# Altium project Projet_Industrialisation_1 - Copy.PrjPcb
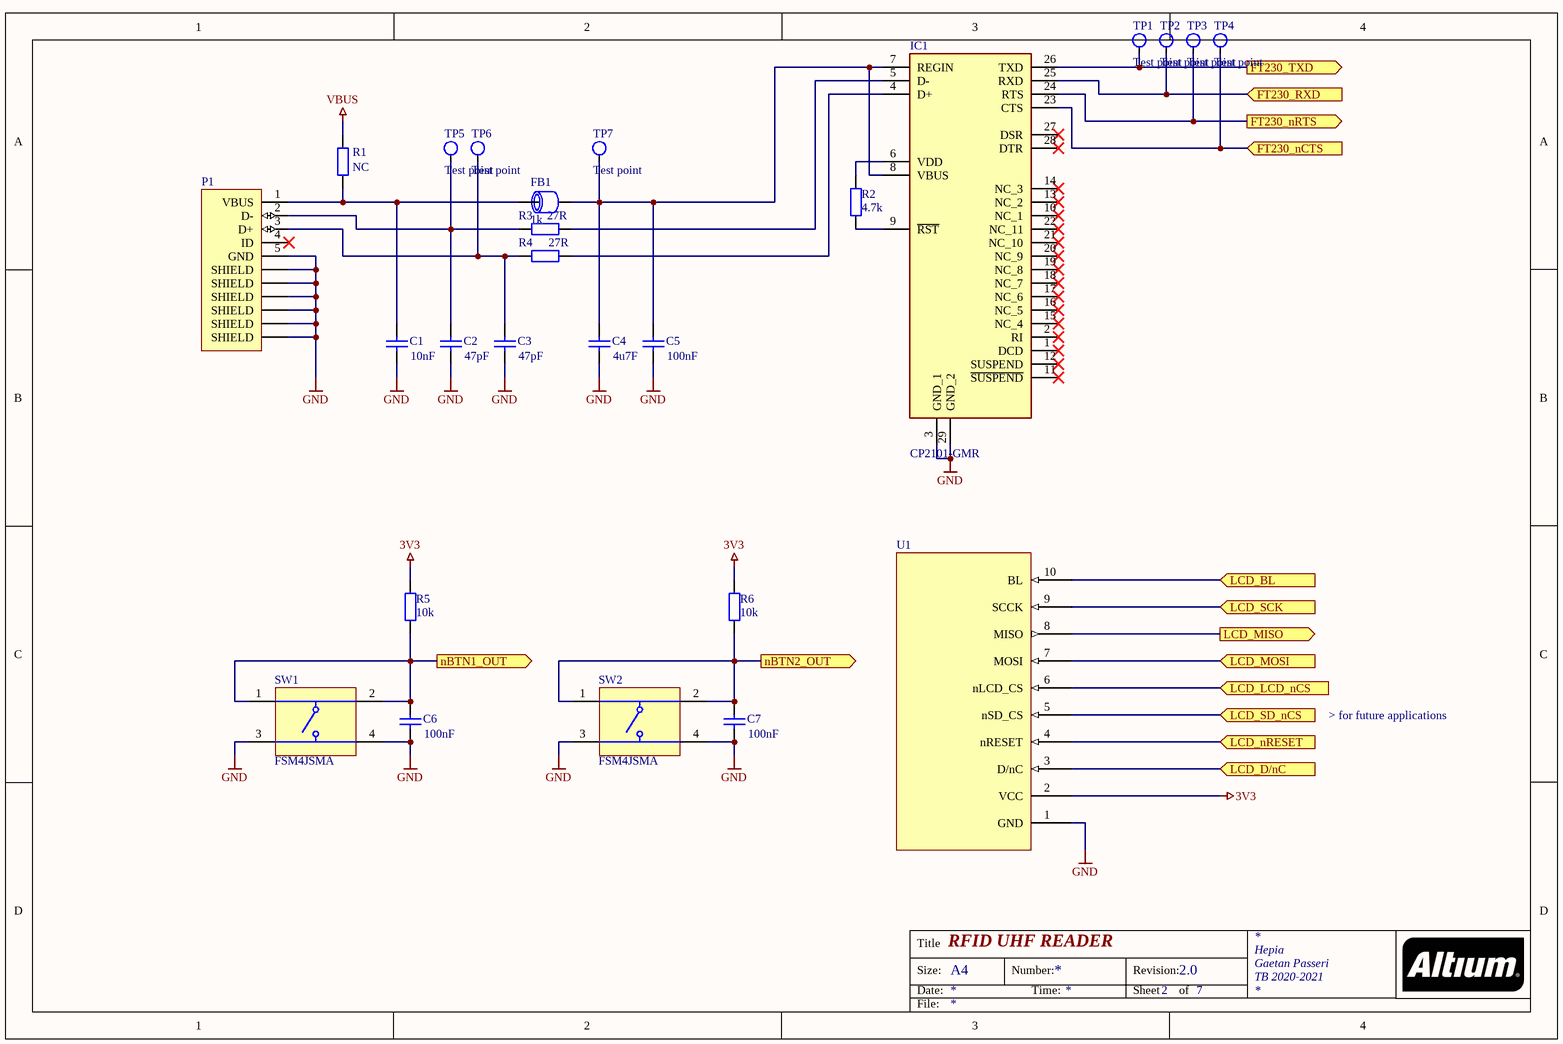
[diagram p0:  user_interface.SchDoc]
7 sheets, 252 parts. Net scope: hierarchical (ports join the sheet entries above them; power ports are global).
Board file:  baseStation.PcbDoc
Sheets:
   user_interface.SchDoc
   rf_interface.SchDoc
   microcontroller.SchDoc
   ext_power_amplifier.SchDoc
   coupling.SchDoc
   baseStation.SchDoc
   alimentation.SchDoc

## Sheet  user_interface.SchDoc: RFID UHF READER
size A4; Date: 19.03.2021; Author: Gaetan Passeri; CompanyName: HEPIA; DrawnBy: Gaetan Passeri; Address1: Hepia; Address2: Gaetan Passeri; Address3: TB 2020-2021; Revision: 2.0; SheetNumber: 2; SheetTotal: 7

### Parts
C1  value 10nF  [FP-C0603C-CF-IPC_B]  (hidden comment: Cap)
C2  value 47pF  [FP-C0603C-CF-IPC_B]  (hidden comment: Cap)
C3  value 47pF  [FP-C0603C-CF-IPC_B]  (hidden comment: Cap)
C4  value 4u7F  [FP-C0603C-CF-IPC_B]  (hidden comment: Cap)
C5  value 100nF  [FP-C0603C-CF-IPC_B]  (hidden comment: Cap)
C6  value 100nF  [FP-C0603C-CF-IPC_B]  (hidden comment: Cap)
C7  value 100nF  [FP-C0603C-CF-IPC_B]  (hidden comment: Cap)
FB1  1k  [L0402-RF]
IC1  CP2101-GMR  [QFN50P500X500X100-29N-D]
P1  47346-0001  [MOLEX_47346-0001]  (value not drawn)
R1  value NC  [FP-RC1608-IPC_B]
R2  value 4.7k  [FP-RC1608-IPC_B]
R3  value 27R  [FP-RC1608-IPC_B]
R4  value 27R  [FP-RC1608-IPC_B]
R5  value 10k  [FP-RC1608-IPC_B]
R6  value 10k  [FP-RC1608-IPC_B]
SW1  FSM4JSMA  [RKB2SJK250SMTRLFS]
SW2  FSM4JSMA  [RKB2SJK250SMTRLFS]
TP1  Test point  [PIN_DE_TEST]
TP2  Test point  [PIN_DE_TEST]
TP3  Test point  [PIN_DE_TEST]
TP4  Test point  [PIN_DE_TEST]
TP5  Test point  [PIN_DE_TEST]
TP6  Test point  [PIN_DE_TEST]
TP7  Test point  [PIN_DE_TEST]
U1  (no value)  [Adafruit_1480]

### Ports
FT230_nCTS (in), FT230_nRTS (out), FT230_RXD (in), FT230_TXD (out), LCD_BL (in), LCD_D/nC (in), LCD_LCD_nCS (in), LCD_MISO (out), LCD_MOSI (in), LCD_nRESET (in), LCD_SCK (in), LCD_SD_nCS (in), nBTN1_OUT (out), nBTN2_OUT (out)

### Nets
3V3: R5.2 R6.2 U1.2(VCC)
GND: C1.1 C2.1 C3.1 C4.1 C5.1 C6.1 C7.1 IC1.3(GND_1) IC1.29(GND_2) P1.5(GND) P1.SH1(SHIELD) P1.SH2(SHIELD) P1.SH3(SHIELD) P1.SH4(SHIELD) P1.SH5(SHIELD) P1.SH6(SHIELD) SW1.3 SW1.4 SW2.3 SW2.4 U1.1(GND)
VBUS: R1.2
NetC1_2: C1.2 FB1.1 P1.1(VBUS) R1.1
NetC2_2: C2.2 P1.2(D-) R3.1 TP5.1(tp)
NetC3_2: C3.2 P1.3(D+) R4.1 TP6.1(tp)
NetC4_2: C4.2 C5.2 FB1.2 IC1.7(REGIN) IC1.8(VBUS) TP7.1(tp)
NetC6_2: C6.2 R5.1 SW1.1 SW1.2 ; port nBTN1_OUT
NetC7_2: C7.2 R6.1 SW2.1 SW2.2 ; port nBTN2_OUT
NetIC1_4: IC1.4(D+) R4.2
NetIC1_5: IC1.5(D-) R3.2
NetIC1_6: IC1.6(VDD) R2.2
NetIC1_9: IC1.9(~{RST}) R2.1
NetIC1_23: IC1.23(CTS) TP4.1(tp) ; port FT230_nCTS
NetIC1_24: IC1.24(RTS) TP3.1(tp) ; port FT230_nRTS
NetIC1_25: IC1.25(RXD) TP2.1(tp) ; port FT230_RXD
NetIC1_26: IC1.26(TXD) TP1.1(tp) ; port FT230_TXD
NetU1_3: U1.3(D/nC) ; port LCD_D/nC
NetU1_4: U1.4(nRESET) ; port LCD_nRESET
NetU1_5: U1.5(nSD_CS) ; port LCD_SD_nCS
NetU1_6: U1.6(nLCD_CS) ; port LCD_LCD_nCS
NetU1_7: U1.7(MOSI) ; port LCD_MOSI
NetU1_8: U1.8(MISO) ; port LCD_MISO
NetU1_9: U1.9(SCCK) ; port LCD_SCK
NetU1_10: U1.10(BL) ; port LCD_BL

Not connected (* = marked no-connect by the designer): IC1 1(DCD)* 2(RI)* 10(NC_1)* 11(~{SUSPEND})* 12(SUSPEND)* 13(NC_2)* 14(NC_3)* 15(NC_4)* 16(NC_5)* 17(NC_6)* 18(NC_7)* 19(NC_8)* 20(NC_9)* 21(NC_10)* 22(NC_11)* 27(DSR)* 28(DTR)*; P1 4(ID)*

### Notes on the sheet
- > for future applications

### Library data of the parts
C1-C7 = Cap: Capacitor
FB1 = BLM15HG102SN1D: FERRITE BEAD 1 KOHM 0402 1LN; Manufacturer: Murata Electronics North America; Filter Type: Signal Line; Number of Lines: 1; Impedance @ Frequency: 1 kOhm @ 100MHz; Current Rating (Max): 250mA; DC Resistance (DCR) (Max): 1.1 Ohm
IC1 = CP2101-GMR: Integrated Circuit; Manufacturer_Name: Silicon Labs
P1 = 47346-0001: USB - micro B USB 2.0 Receptacle Connector 5 Position Surface Mount, Right Angle; MF: Molex
R1-R6 = Res2: Resistor
SW1 SW2 = CMP-2000-05602-2: Swicth, SPST, 24 V, -35 to 85 degC, 4-Pin SMD, RoHS, Tape and Reel; Manufacturer: TE Connectivity; Switch Travel: 0.25mm; Mechanical Life: 100000Cycles; Contact Current Rating: 50mA; Operating Force: 1.57N; Actuator Material: Polyamide; Contact Resistance: 100mOhm; Voltage Rating: 24V; Illumination Type: Illuminated; Actuator Length: 0.055inch; Max Voltage Rating (DC): 12V; Case\/Package: SMD/SMT
TP1-TP7 = TestPoint
U1 = Adafruit_1480: LCD Module Adafruit 1480, SPI 320x240p 2.2"

## Sheet  rf_interface.SchDoc: RFID UHF READER
size A3; Author: Gaetan Passeri; CompanyName: Hepia; Address1: Hepia; Address2: Gaetan Passeri; Address3: TB 2020-2021; Revision: 2.0; SheetNumber: 3; SheetTotal: 7
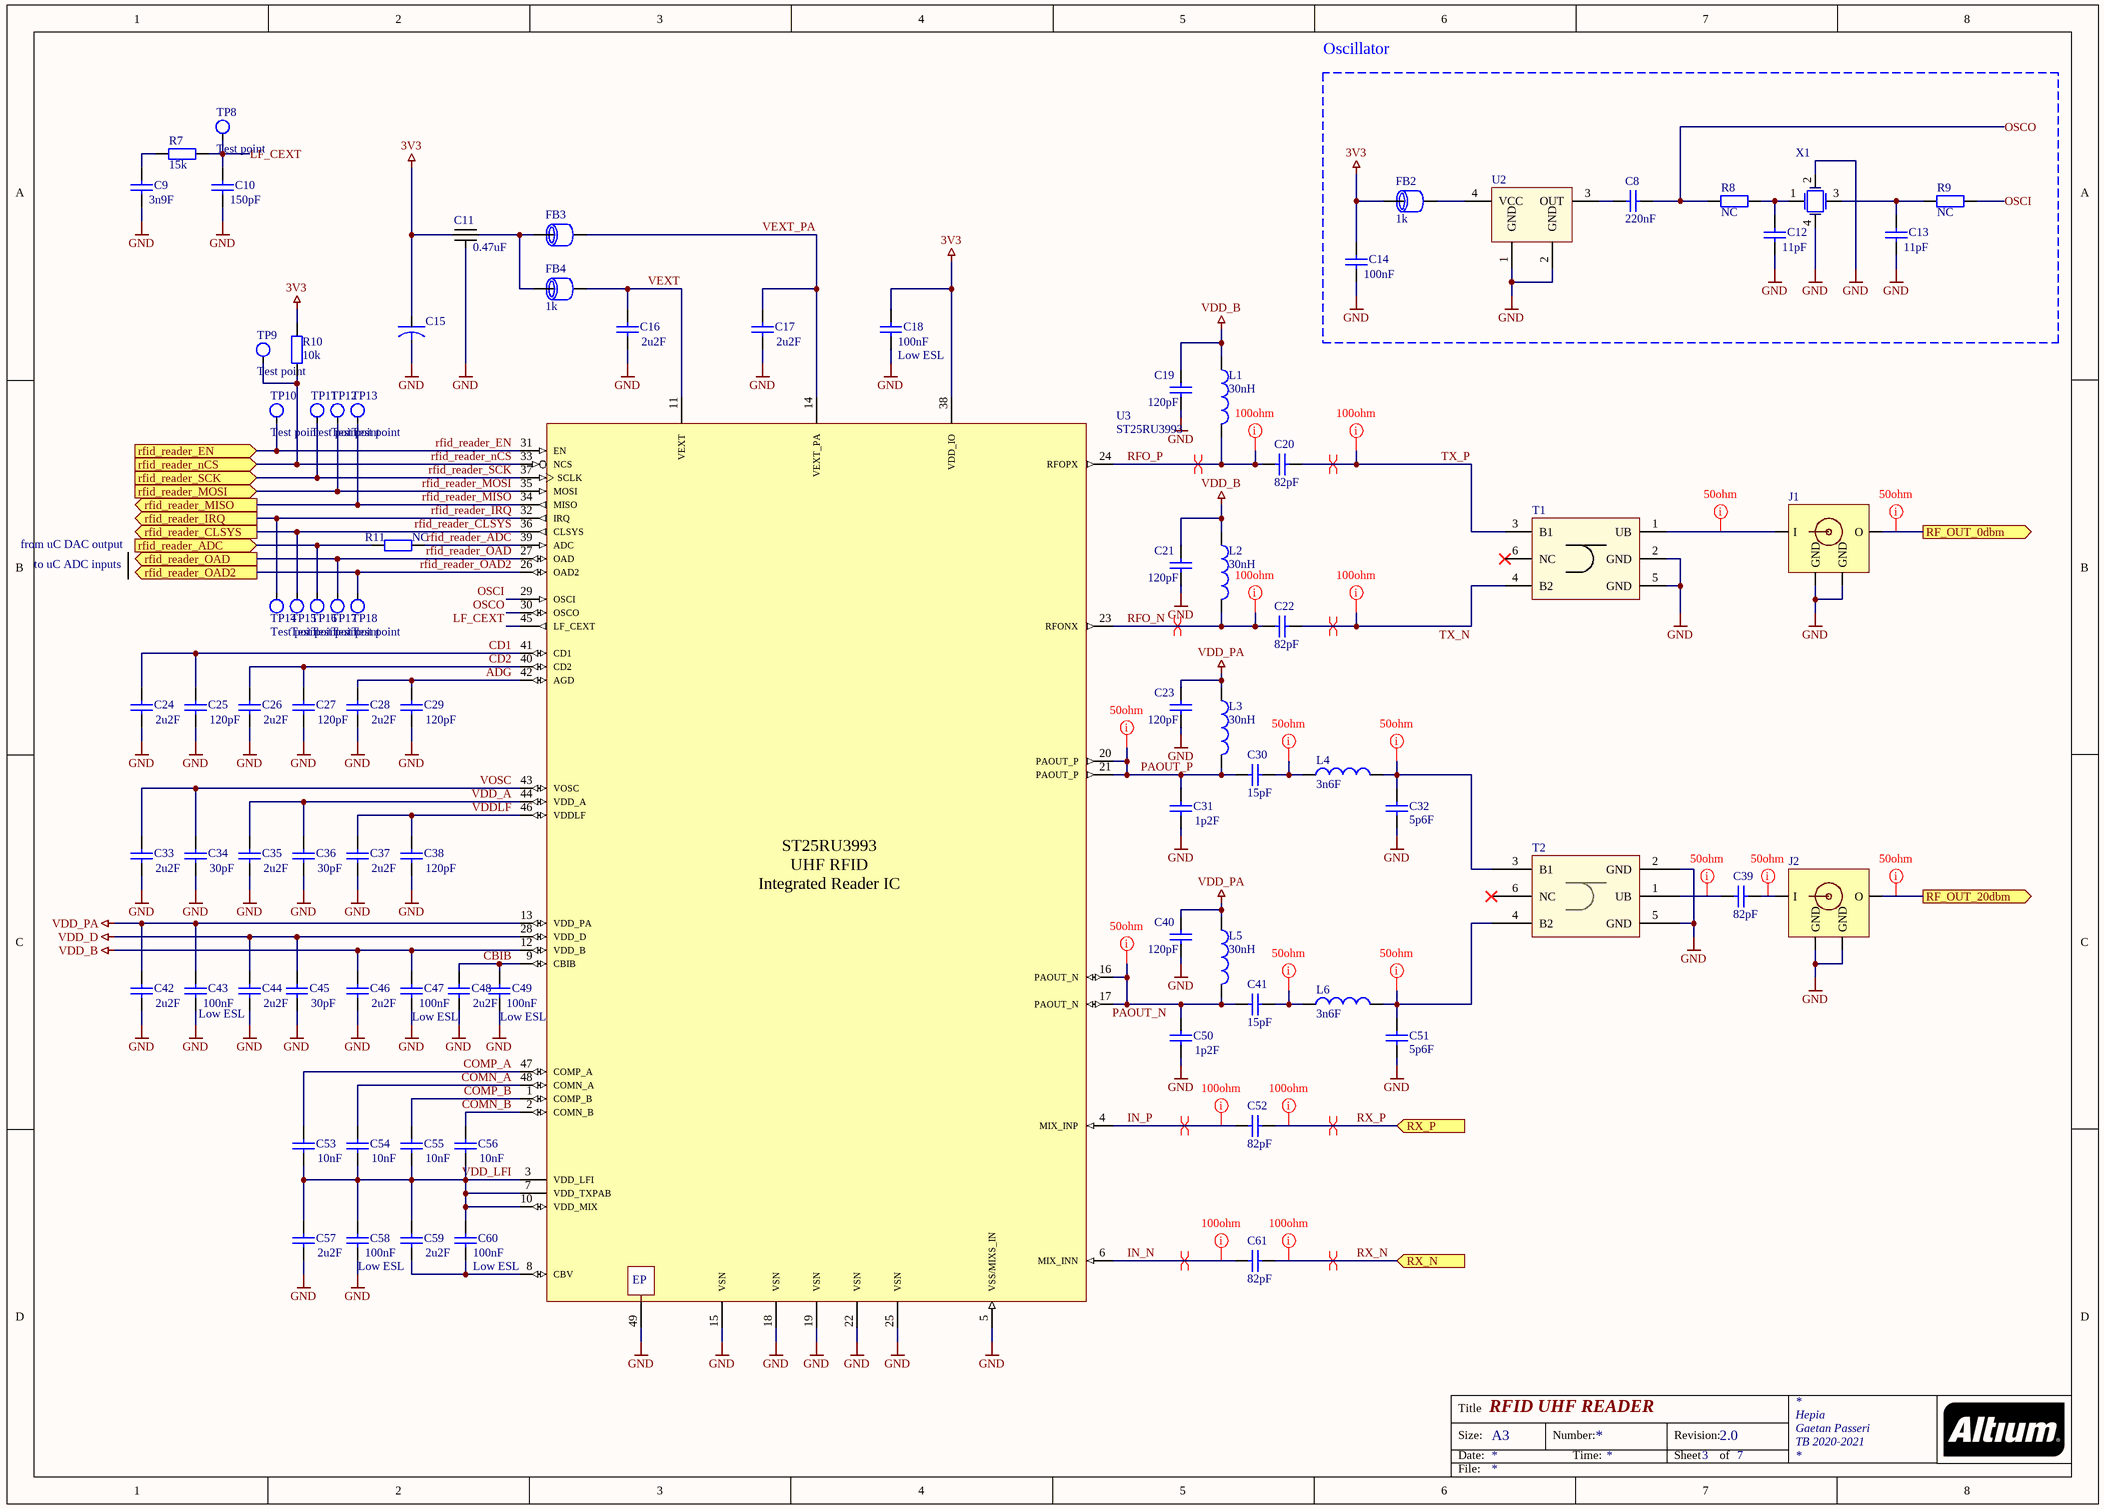
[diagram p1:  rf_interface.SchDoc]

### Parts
C8  value 220nF  [FP-C0603C-CF-IPC_B]
C9  value 3n9F  [FP-PRF15-0_05-IPC_A]
C10  value 150pF  [FP-PRF15-0_05-IPC_A]
C11  0.47uF  [NFM18PS]
C12  value 11pF  [FP-C0603C-CF-IPC_B]
C13  value 11pF  [FP-C0603C-CF-IPC_B]
C14  value 100nF  [FP-C0603C-CF-IPC_B]
C15  (no value)  [2917(7343)]
C16  value 2u2F  [FP-PRF15-0_05-IPC_A]  (hidden comment: Cap)
C17  value 2u2F  [FP-PRF15-0_05-IPC_A]  (hidden comment: Cap)
C18  Low ESL  value 100nF  [FP-PRF15-0_05-IPC_A]
C19  value 120pF  [FP-PRF15-0_05-IPC_A]  (hidden comment: Cap)
C20  value 82pF  [FP-PRF15-0_05-IPC_A]  (hidden comment: Cap)
C21  value 120pF  [FP-PRF15-0_05-IPC_A]  (hidden comment: Cap)
C22  value 82pF  [FP-PRF15-0_05-IPC_A]  (hidden comment: Cap)
C23  value 120pF  [FP-PRF15-0_05-IPC_A]  (hidden comment: Cap)
C24  value 2u2F  [FP-PRF15-0_05-IPC_A]  (hidden comment: Cap)
C25  value 120pF  [FP-PRF15-0_05-IPC_A]  (hidden comment: Cap)
C26  value 2u2F  [FP-PRF15-0_05-IPC_A]  (hidden comment: Cap)
C27  value 120pF  [FP-PRF15-0_05-IPC_A]  (hidden comment: Cap)
C28  value 2u2F  [FP-PRF15-0_05-IPC_A]  (hidden comment: Cap)
C29  value 120pF  [FP-PRF15-0_05-IPC_A]  (hidden comment: Cap)
C30  value 15pF  [FP-PRF15-0_05-IPC_A]  (hidden comment: Cap)
C31  value 1p2F  [FP-PRF15-0_05-IPC_A]  (hidden comment: Cap)
C32  value 5p6F  [FP-PRF15-0_05-IPC_A]  (hidden comment: Cap)
C33  value 2u2F  [FP-PRF15-0_05-IPC_A]  (hidden comment: Cap)
C34  value 30pF  [FP-PRF15-0_05-IPC_A]  (hidden comment: Cap)
C35  value 2u2F  [FP-PRF15-0_05-IPC_A]  (hidden comment: Cap)
C36  value 30pF  [FP-PRF15-0_05-IPC_A]  (hidden comment: Cap)
C37  value 2u2F  [FP-PRF15-0_05-IPC_A]  (hidden comment: Cap)
C38  value 120pF  [FP-PRF15-0_05-IPC_A]  (hidden comment: Cap)
C39  value 82pF  [FP-C0603C-CF-IPC_B]  (hidden comment: Cap)
C40  value 120pF  [FP-PRF15-0_05-IPC_A]  (hidden comment: Cap)
C41  value 15pF  [FP-PRF15-0_05-IPC_A]  (hidden comment: Cap)
C42  value 2u2F  [FP-PRF15-0_05-IPC_A]  (hidden comment: Cap)
C43  Low ESL  value 100nF  [FP-PRF15-0_05-IPC_A]
C44  value 2u2F  [FP-PRF15-0_05-IPC_A]  (hidden comment: Cap)
C45  value 30pF  [FP-PRF15-0_05-IPC_A]  (hidden comment: Cap)
C46  value 2u2F  [FP-PRF15-0_05-IPC_A]  (hidden comment: Cap)
C47  Low ESL  value 100nF  [FP-PRF15-0_05-IPC_A]
C48  value 2u2F  [FP-PRF15-0_05-IPC_A]  (hidden comment: Cap)
C49  Low ESL  value 100nF  [FP-PRF15-0_05-IPC_A]
C50  value 1p2F  [FP-PRF15-0_05-IPC_A]  (hidden comment: Cap)
C51  value 5p6F  [FP-PRF15-0_05-IPC_A]  (hidden comment: Cap)
C52  value 82pF  [FP-PRF15-0_05-IPC_A]  (hidden comment: Cap)
C53  value 10nF  [FP-PRF15-0_05-IPC_A]  (hidden comment: Cap)
C54  value 10nF  [FP-PRF15-0_05-IPC_A]  (hidden comment: Cap)
C55  value 10nF  [FP-PRF15-0_05-IPC_A]  (hidden comment: Cap)
C56  value 10nF  [FP-PRF15-0_05-IPC_A]  (hidden comment: Cap)
C57  value 2u2F  [FP-PRF15-0_05-IPC_A]  (hidden comment: Cap)
C58  Low ESL  value 100nF  [FP-PRF15-0_05-IPC_A]
C59  value 2u2F  [FP-PRF15-0_05-IPC_A]  (hidden comment: Cap)
C60  Low ESL  value 100nF  [FP-PRF15-0_05-IPC_A]
C61  value 82pF  [FP-PRF15-0_05-IPC_A]  (hidden comment: Cap)
FB2  1k  [L0402-RF]
FB3  (no value)  [FB0402-RF]
FB4  1k  [L0402-RF]
J1  (no value)  [MS-156HF]
J2  (no value)  [MS-156HF]
L1  value 30nH  [FP-LQG15HH_02-IPC_A]  (hidden comment: Inductor)
L2  value 30nH  [FP-LQG15HH_02-IPC_A]  (hidden comment: Inductor)
L3  value 30nH  [FP-LQG15HH_02-IPC_A]  (hidden comment: Inductor)
L4  value 3n6F  [FP-LQG15HH_02-IPC_A]  (hidden comment: Inductor)
L5  value 30nH  [FP-LQG15HH_02-IPC_A]  (hidden comment: Inductor)
L6  value 3n6F  [FP-LQG15HH_02-IPC_A]  (hidden comment: Inductor)
R7  value 15k  [FP-RC1608-IPC_B]
R8  value NC  [FP-RC1608-IPC_B]
R9  value NC  [FP-RC1608-IPC_B]
R10  value 10k  [FP-RC1608-IPC_B]
R11  value NC  [FP-RC1608-IPC_B]
T1  (no value)  [BD0810J50100AHF]
T2  (no value)  [JTI-0900BL15C050]
TP8  Test point  [PIN_DE_TEST]
TP9  Test point  [PIN_DE_TEST]
TP10  Test point  [PIN_DE_TEST]
TP11  Test point  [PIN_DE_TEST]
TP12  Test point  [PIN_DE_TEST]
TP13  Test point  [PIN_DE_TEST]
TP14  Test point  [PIN_DE_TEST]
TP15  Test point  [PIN_DE_TEST]
TP16  Test point  [PIN_DE_TEST]
TP17  Test point  [PIN_DE_TEST]
TP18  Test point  [PIN_DE_TEST]
U2  (no value)  [TY_TYPE_2.5x2.0mm]
U3  ST25RU3993  [ST25RU3993_QFN48_0.5mm_pitch]
X1  (no value)  [NX3225SA]

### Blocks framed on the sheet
Oscillator: C8 C12-C14 FB2 R8 R9 U2 X1

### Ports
RF_OUT_0dbm (out), RF_OUT_20dbm (out), rfid_reader_ADC (in), rfid_reader_CLSYS (out), rfid_reader_EN (in), rfid_reader_IRQ (out), rfid_reader_MISO (out), rfid_reader_MOSI (in), rfid_reader_nCS (in), rfid_reader_OAD2 (out), rfid_reader_OAD (out), rfid_reader_SCK (in), RX_N (in), RX_P (in)

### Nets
3V3: C11.1 C14.1 C15.1 C18.1 FB2.1 R10.1 U3.38(VDD_IO)
GND: C9.2 C10.2 C11.2 C12.2 C13.2 C14.2 C15.2 C16.2 C17.2 C18.2 C19.2 C21.2 C23.2 C24.2 C25.2 C26.2 C27.2 C28.2 C29.2 C31.2 C32.1 C33.2 C34.2 C35.2 C36.2 C37.2 C38.2 C40.2 C42.2 C43.2 C44.2 C45.2 C46.2 C47.2 C48.2 C49.2 C50.2 C51.1 C57.2 C58.2 J1.G1(GND) J1.G2(GND) J2.G1(GND) J2.G2(GND) T1.2(GND) T1.5(GND) T2.2(GND) T2.5(GND) U2.1(GND) U2.2(GND) U3.5(VSS/MIXS_IN) U3.15(VSN) U3.18(VSN) U3.19(VSN) U3.22(VSN) U3.25(VSN) U3.49(EP) X1.2(GND) X1.4(GND)
VDD_B: C19.1 C21.1 C46.1 C47.1 L1.1 L2.1 U3.12(VDD_B)
VDD_D: C44.1 C45.1 U3.28(VDD_D)
VDD_PA: C23.1 C40.1 C42.1 C43.1 L3.1 L5.1 U3.13(VDD_PA)
ADG: C28.1 C29.1 U3.42(AGD)
CBIB: C48.1 C49.1 U3.9(CBIB)
CD1: C24.1 C25.1 U3.41(CD1)
CD2: C26.1 C27.1 U3.40(CD2)
COMN_A: C54.1 U3.48(COMN_A)
COMN_B: C56.1 U3.2(COMN_B)
COMP_A: C53.1 U3.47(COMP_A)
COMP_B: C55.1 U3.1(COMP_B)
IN_N: C61.1 U3.6(MIX_INN)
IN_P: C52.1 U3.4(MIX_INP)
LF_CEXT: C10.1 R7.1 TP8.1(tp) U3.45(LF_CEXT)
OSCI: R9.1 U3.29(OSCI)
OSCO: C8.2 R8.2 U3.30(OSCO)
PAOUT_N: C41.1 C50.1 L5.2 U3.16(PAOUT_N) U3.17(PAOUT_N)
PAOUT_P: C30.1 C31.1 L3.2 U3.20(PAOUT_P) U3.21(PAOUT_P)
rfid_reader_ADC: R11.2 U3.39(ADC)
rfid_reader_CLSYS: TP15.1(tp) U3.36(CLSYS) ; port rfid_reader_CLSYS
rfid_reader_EN: TP10.1(tp) U3.31(EN) ; port rfid_reader_EN
rfid_reader_IRQ: TP14.1(tp) U3.32(IRQ) ; port rfid_reader_IRQ
rfid_reader_MISO: TP13.1(tp) U3.34(MISO) ; port rfid_reader_MISO
rfid_reader_MOSI: TP12.1(tp) U3.35(MOSI) ; port rfid_reader_MOSI
rfid_reader_nCS: R10.2 TP9.1(tp) U3.33(NCS) ; port rfid_reader_nCS
rfid_reader_OAD: TP17.1(tp) U3.27(OAD) ; port rfid_reader_OAD
rfid_reader_OAD2: TP18.1(tp) U3.26(OAD2) ; port rfid_reader_OAD2
rfid_reader_SCK: TP11.1(tp) U3.37(SCLK) ; port rfid_reader_SCK
RFO_N: C22.1 L2.2 U3.23(RFONX)
RFO_P: C20.1 L1.2 U3.24(RFOPX)
RX_N: C61.2 ; port RX_N
RX_P: C52.2 ; port RX_P
TX_N: C22.2 T1.4(B2)
TX_P: C20.2 T1.3(B1)
VDD_A: C35.1 C36.1 U3.44(VDD_A)
VDD_LFI: C53.2 C54.2 C55.2 C56.2 C57.1 C58.1 C59.1 C60.1 U3.3(VDD_LFI) U3.7(VDD_TXPAB) U3.10(VDD_MIX)
VDDLF: C37.1 C38.1 U3.46(VDDLF)
VEXT: C16.1 FB4.2 U3.11(VEXT)
VEXT_PA: C17.1 FB3.2 U3.14(VEXT_PA)
VOSC: C33.1 C34.1 U3.43(VOSC)
NetC8_1: C8.1 U2.3(OUT)
NetC9_1: C9.1 R7.2
NetC11_3: C11.3 FB3.1 FB4.1
NetC12_1: C12.1 R8.1 X1.1
NetC13_1: C13.1 R9.2 X1.3
NetC30_2: C30.2 L4.1
NetC32_2: C32.2 L4.2 T2.3(B1)
NetC39_1: C39.1 T2.1(UB)
NetC39_2: C39.2 J2.IN(I)
NetC41_2: C41.2 L6.1
NetC51_2: C51.2 L6.2 T2.4(B2)
NetC59_2: C59.2 C60.2 U3.8(CBV)
NetFB2_2: FB2.2 U2.4(VCC)
NetJ1_IN: J1.IN(I) T1.1(UB)
NetJ1_OUT: J1.OUT(O) ; port RF_OUT_0dbm
NetJ2_OUT: J2.OUT(O) ; port RF_OUT_20dbm
NetR11_1: R11.1 TP16.1(tp) ; port rfid_reader_ADC

Not connected (* = marked no-connect by the designer): T1 6(NC)*; T2 6(NC)*

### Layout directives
rule Impedance Constraint [Min = 50.00    Max = 50.00    ]: NetC30_2, NetC32_2, NetC39_1, NetC39_2, NetC41_2, NetC51_2, NetJ1_IN, NetJ1_OUT, NetJ2_OUT, PAOUT_N, PAOUT_P
rule Impedance Constraint [Min = 100.0    Max = 100.0    ]: IN_N, IN_P, RFO_N, RFO_P, RX_N, RX_P, TX_N, TX_P
differential pair: IN_N, IN_P, RFO_N, RFO_P, RX_N, RX_P, TX_N, TX_P

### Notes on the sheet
- (near C12) The TCXO is used by default. To use crystal instead, unconnect C ...(220nF) and connect two 0ohms.
- from uC DAC output
- to uC ADC inputs

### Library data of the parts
C8-C10 C12-C14 C16-C61 = Cap: type : free, 0603, 20%
C11 = NFM18PS474R0J3D_1: CAP FEEDTHRU 0.47UF 6.3V 0603; Manufacturer: Murata Electronics North America; Capacitance: 0.47µF; Tolerance: ±20%; Current: 2A; DC Resistance (DCR) (Max): 30 mOhm; Type: Polymer; ESR (Equivalent Series Resistance): 70 mOhm; Lifetime @ Temp.: 1000 Hrs @ 105°C; Ripple Current - High Frequency: 1A @ 100kHz; Surface Mount Land Size: 0.287" L x 0.169" W (7.30mm x 4.30mm)
C15 = ECASD41C106M060K00: CAP POLYMER 10UF 20% 16V SMD; Manufacturer: Murata; Product Training Modules: Polymer Aluminum Electrolytic Capacitors Using Murata's Polymer Aluminum Capacitors to Replace Tantalum; Catalog Drawings: ECAS Series End_D4 ECAS Series Side; Featured Product: ECAS Series Polymer Aluminum Electrolytic Capacitors; EDA / CAD Models: Download from Accelerated Designs; Capacitance: 10µF; ESR (Equivalent Series Resistance): 60 mOhm @ 100kHz; Lifetime @ Temp.: 1000 Hrs @ 105°C; Polarization: Polar; Ripple Current: 1A; Surface Mount Land Size: 0.287" L x 0.169" W (7.30mm x 4.30mm); Online Catalog: ECAS Series; Other Names: 490-5482-2
FB2 FB4 = BLM15HG102SN1D: as FB1 on sheet  user_interface
FB3 = BLM15PX331SN1D: FERRITE BEAD 330 OHM 0402 1LN; Manufacturer: Murata Electronics North America; Filter Type: Power Line; Current Rating (Max): 1.2A; DC Resistance (DCR) (Max): 150 mOhm
J1 J2 = MS-156HF: CONN COAX JACK STR 50 OHM SMD; Manufacturer 1: Hirose Electric Co Ltd; Manufacturer Part Number 1: MS-156HF(01); Connector Style: Coaxial Switch - 4mm Plug Dia; Connector Type: Receptacle, Female Socket; Contact Termination: Solder; Impedance: 50 Ohm; Frequency - Max: 6GHz; Body Material: Phosphor Bronze; Body Finish: Gold; Center Contact Material: Beryllium Copper; Dielectric Material: Polyamide (PA), Nylon 6T; Coupler Type: Standard; Frequency: 700MHz ~ 1GHz; Coupling Factor: 10.9dB; Insertion Loss: 0.21dB; Power - Max: 2W; Return Loss: 17.5dB; Exact Component Match: yes
L1-L6 = Inductor: Code_IEC: 1005
R7-R11 = Res2: Resistor
T1 = BD0810J50100AHF: XFRMR BALUN RF 800-1000MHZ 0805; Manufacturer: Anaren; Frequency Range: 800MHz ~ 1GHz; Impedance - Unbalanced/Balanced: 50 / 100 Ohm; Phase Difference: 1°; Insertion Loss (Max): 0.95dB; Return Loss (Min): 13dB
T2 = 1:1 BALUN 900MHZ - 0900BL15C050: 1:1 BALUN- 900MHZ 50/50 Ohm; Manufacturer: Johanson Technology Inc; Manufacturer Part Number: 0900BL15C050E; Component_Description: BALUN GSM/DCS/PCS/CDMA 900MHZ; Frequency Range: 800 ~ 1000MHz; Phase Difference: 180° ±10; Insertion Loss (Max): 1.2dB; Return Loss (Min): 9.5dB
TP8-TP18 = TestPoint
U2 = 7Q-20.000MCN-T: OSC TCXO 20.000MHZ CLPD SNWV SMD; Manufacturer: Taitien; Manufacturer Part Number: TXEAADSANF-20.000000; Output: Clipped Sine Wave; Voltage - Supply: 2.8 V ~ 3.3 V; Frequency Stability: ±500ppb; Current - Supply (Max): 2mA
U3 = ST25RU3993: UHF EPC CLASS1 GEN2 READER; Manufacturer: ST Microelectronics; Manufacturer Part Number: AS3993-BQFT; Frequency: 860MHz ~ 960MHz; Standards: EPC, ISO 18000-6; Voltage - Supply: 2.7 V ~ 3.6 V; Exact Component Match: yes
X1 = NX3225SA-20.000000MHZ-B2: CRYSTAL 20.0000MHZ 7.2PF SMD; Manufacturer: NDK; Frequency: 20MHz; Frequency Stability: ±15ppm; Frequency Tolerance: ±10ppm; ESR (Equivalent Series Resistance): 80 Ohm; Operating Mode: Fundamental

## Sheet  microcontroller.SchDoc: RFID UHF READER
size A3; Date: 19.03.2021; Author: Gaetan Passeri; CompanyName: HEPIA; DrawnBy: Gaetan Passeri; Address1: Hepia; Address2: Gaetan Passeri; Address3: TB 2020-2021; Revision: 2.0; SheetNumber: 4; SheetTotal: 7
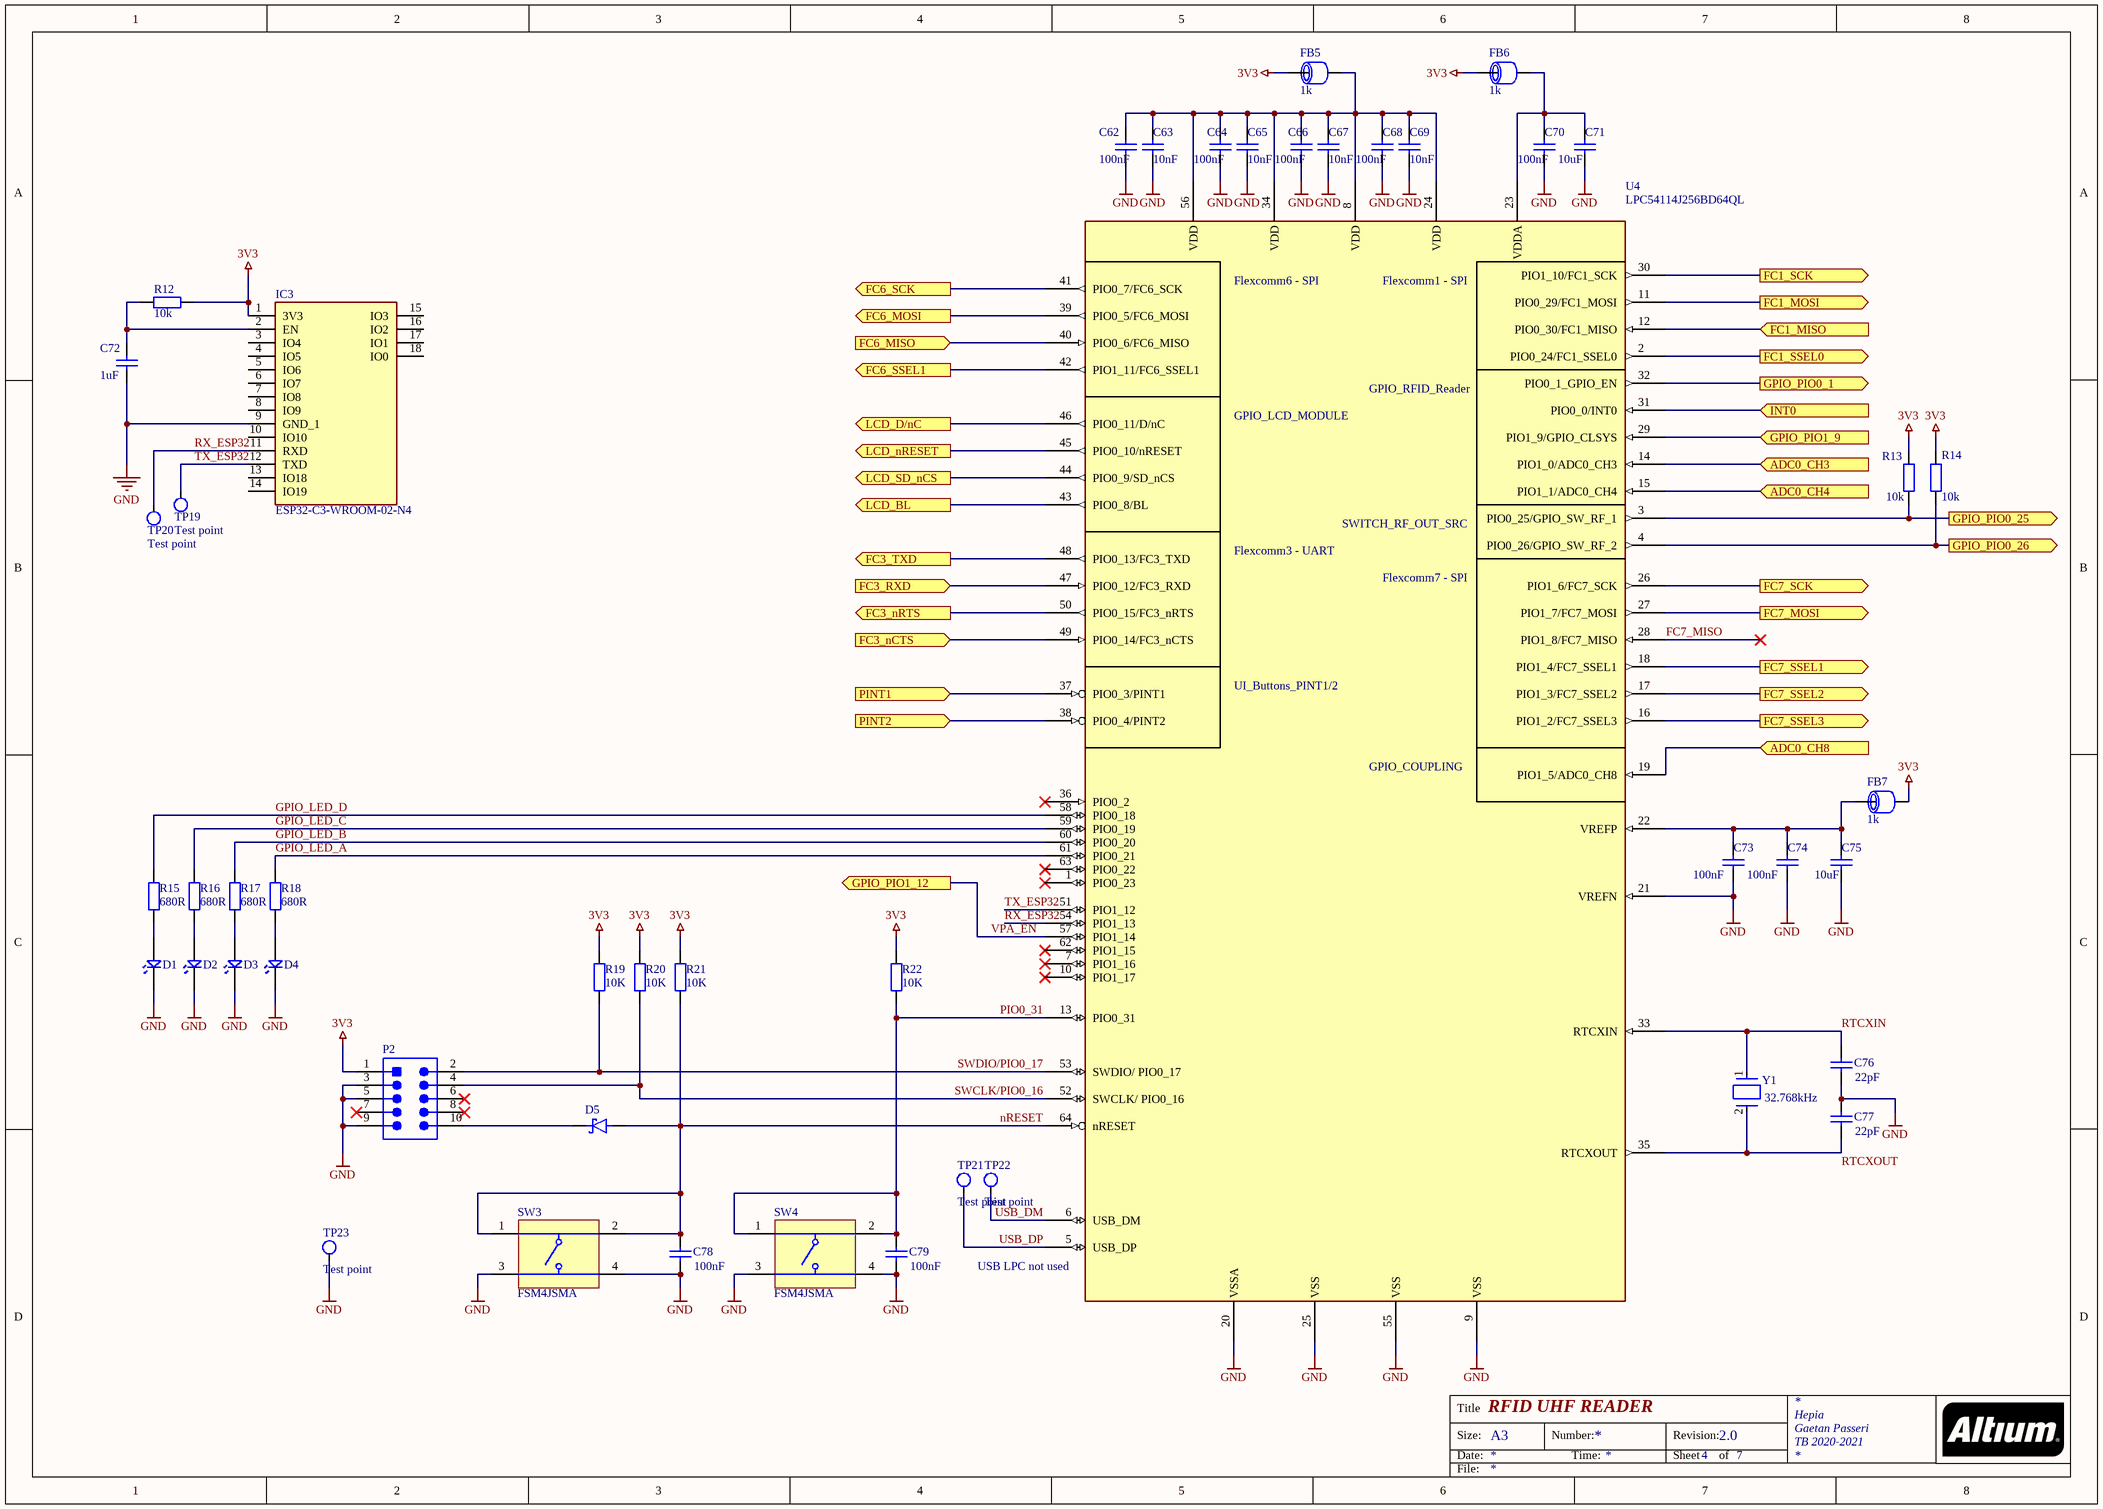
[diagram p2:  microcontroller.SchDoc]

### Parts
C62  value 100nF  [FP-C0603C-CF-IPC_A]  (hidden comment: Cap)
C63  value 10nF  [FP-C0603C-CF-IPC_A]  (hidden comment: Cap)
C64  value 100nF  [FP-C0603C-CF-IPC_A]  (hidden comment: Cap)
C65  value 10nF  [FP-C0603C-CF-IPC_A]  (hidden comment: Cap)
C66  value 100nF  [FP-C0603C-CF-IPC_A]  (hidden comment: Cap)
C67  value 10nF  [FP-C0603C-CF-IPC_A]  (hidden comment: Cap)
C68  value 100nF  [FP-C0603C-CF-IPC_A]  (hidden comment: Cap)
C69  value 10nF  [FP-C0603C-CF-IPC_A]  (hidden comment: Cap)
C70  value 100nF  [FP-C0603C-CF-IPC_A]  (hidden comment: Cap)
C71  value 10uF  [FP-C0603C-CF-IPC_A]  (hidden comment: Cap)
C72  value 1uF  [FP-C0603C-CF-IPC_A]  (hidden comment: Cap)
C73  value 100nF  [FP-C0603C-CF-IPC_A]  (hidden comment: Cap)
C74  value 100nF  [FP-C0603C-CF-IPC_A]  (hidden comment: Cap)
C75  value 10uF  [FP-C0603C-CF-IPC_A]  (hidden comment: Cap)
C76  value 22pF  [FP-C0603C-CF-IPC_A]  (hidden comment: Cap)
C77  value 22pF  [FP-C0603C-CF-IPC_A]  (hidden comment: Cap)
C78  value 100nF  [FP-C0603C-CF-IPC_B]  (hidden comment: Cap)
C79  value 100nF  [FP-C0603C-CF-IPC_B]  (hidden comment: Cap)
D1  (no value)  [LTST-C170KRKT_V]
D2  (no value)  [LTST-C170KRKT_V]
D3  (no value)  [LTST-C170KRKT_V]
D4  (no value)  [LTST-C170KRKT_V]
D5  (no value)  [SOD3715X135N]
FB5  1k  [L0402-RF]
FB6  1k  [L0402-RF]
FB7  1k  [L0402-RF]
IC3  ESP32-C3-WROOM-02-N4  [ESP32C3WROOM02N4]
P2  (no value)  [HDR2X5_SMT]
R12  value 10k  [FP-RC1608-IPC_B]
R13  value 10k  [FP-RC1608-IPC_B]
R14  value 10k  [FP-RC1608-IPC_B]
R15  value 680R  [FP-RC1608-IPC_B]
R16  value 680R  [FP-RC1608-IPC_B]
R17  value 680R  [FP-RC1608-IPC_B]
R18  value 680R  [FP-RC1608-IPC_B]
R19  value 10K  [FP-RC1608-IPC_A]
R20  value 10K  [FP-RC1608-IPC_A]
R21  value 10K  [FP-RC1608-IPC_A]
R22  value 10K  [FP-RC1608-IPC_A]
SW3  FSM4JSMA  [RKB2SJK250SMTRLFS]
SW4  FSM4JSMA  [RKB2SJK250SMTRLFS]
TP19  Test point  [PIN_DE_TEST]
TP20  Test point  [PIN_DE_TEST]
TP21  Test point  [PIN_DE_TEST]
TP22  Test point  [PIN_DE_TEST]
TP23  Test point  [PIN_DE_TEST]
U4  LPC54114J256BD64QL  [QFP50P1200X1200X160-64N]
Y1  Frequency: 32.768kHz  [FP-ECX-34Q-MFG]

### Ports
ADC0_CH3 (in), ADC0_CH4 (in), ADC0_CH8 (in), FC1_MISO (in), FC1_MOSI (out), FC1_SCK (out), FC1_SSEL0 (out), FC3_nCTS (in), FC3_nRTS (out), FC3_RXD (in), FC3_TXD (out), FC6_MISO (in), FC6_MOSI (out), FC6_SCK (out), FC6_SSEL1 (out), FC7_MOSI (out), FC7_SCK (out), FC7_SSEL1 (out), FC7_SSEL2 (out), FC7_SSEL3 (out), GPIO_PIO0_1 (out), GPIO_PIO0_25 (out), GPIO_PIO0_26 (out), GPIO_PIO1_9 (in), GPIO_PIO1_12 (out), INT0 (in), LCD_BL (out), LCD_D/nC (out), LCD_nRESET (out), LCD_SD_nCS (out), PINT1 (in), PINT2 (in)

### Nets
3V3: FB5.1 FB6.1 FB7.2 IC3.1(3V3) P2.1 R12.2 R13.1 R14.1 R19.2 R20.2 R21.2 R22.2
GND: C62.1 C63.1 C64.1 C65.1 C66.1 C67.1 C68.1 C69.1 C70.1 C71.1 C72.1 C73.1 C74.1 C75.1 C76.1 C77.2 C78.1 C79.1 D1.K D2.K D3.K D4.K IC3.9(GND_1) P2.3 P2.5 P2.9 SW3.3 SW3.4 SW4.3 SW4.4 TP23.1(tp) U4.9(VSS) U4.20(VSSA) U4.21(VREFN) U4.25(VSS) U4.55(VSS)
FC7_MISO: U4.28(PIO1_8/FC7_MISO)
GPIO_LED_A: R18.2 U4.61(PIO0_21)
GPIO_LED_B: R17.2 U4.60(PIO0_20)
GPIO_LED_C: R16.2 U4.59(PIO0_19)
GPIO_LED_D: R15.2 U4.58(PIO0_18)
nRESET: C78.2 D5.A R21.1 SW3.1 SW3.2 U4.64(nRESET)
PIO0_31: C79.2 R22.1 SW4.1 SW4.2 U4.13(PIO0_31)
RTCXIN: C76.2 U4.33(RTCXIN) Y1.1(In/Out)
RTCXOUT: C77.1 U4.35(RTCXOUT) Y1.2(Out/In)
RX_ESP32: IC3.11(RXD) TP20.1(tp) U4.54(PIO1_13)
SWCLK/PIO0_16: P2.4 R20.1 U4.52(SWCLK/_PIO0_16)
SWDIO/PIO0_17: P2.2 R19.1 U4.53(SWDIO/_PIO0_17)
TX_ESP32: IC3.12(TXD) TP19.1(tp) U4.51(PIO1_12)
USB_DM: TP22.1(tp) U4.6(USB_DM)
USB_DP: TP21.1(tp) U4.5(USB_DP)
VPA_EN: U4.57(PIO1_14) ; port GPIO_PIO1_12
NetC62_2: C62.2 C63.2 C64.2 C65.2 C66.2 C67.2 C68.2 C69.2 FB5.2 U4.8(VDD) U4.24(VDD) U4.34(VDD) U4.56(VDD)
NetC70_2: C70.2 C71.2 FB6.2 U4.23(VDDA)
NetC72_2: C72.2 IC3.2(EN) R12.1
NetC73_2: C73.2 C74.2 C75.2 FB7.1 U4.22(VREFP)
NetD1_A: D1.A R15.1
NetD2_A: D2.A R16.1
NetD3_A: D3.A R17.1
NetD4_A: D4.A R18.1
NetD5_K: D5.K P2.10
NetR13_2: R13.2 U4.3(PIO0_25/GPIO_SW_RF_1) ; port GPIO_PIO0_25
NetR14_2: R14.2 U4.4(PIO0_26/GPIO_SW_RF_2) ; port GPIO_PIO0_26
NetU4_2: U4.2(PIO0_24/FC1_SSEL0) ; port FC1_SSEL0
NetU4_11: U4.11(PIO0_29/FC1_MOSI) ; port FC1_MOSI
NetU4_12: U4.12(PIO0_30/FC1_MISO) ; port FC1_MISO
NetU4_14: U4.14(PIO1_0/ADC0_CH3) ; port ADC0_CH3
NetU4_15: U4.15(PIO1_1/ADC0_CH4) ; port ADC0_CH4
NetU4_16: U4.16(PIO1_2/FC7_SSEL3) ; port FC7_SSEL3
NetU4_17: U4.17(PIO1_3/FC7_SSEL2) ; port FC7_SSEL2
NetU4_18: U4.18(PIO1_4/FC7_SSEL1) ; port FC7_SSEL1
NetU4_19: U4.19(PIO1_5/ADC0_CH8) ; port ADC0_CH8
NetU4_26: U4.26(PIO1_6/FC7_SCK) ; port FC7_SCK
NetU4_27: U4.27(PIO1_7/FC7_MOSI) ; port FC7_MOSI
NetU4_29: U4.29(PIO1_9/GPIO_CLSYS) ; port GPIO_PIO1_9
NetU4_30: U4.30(PIO1_10/FC1_SCK) ; port FC1_SCK
NetU4_31: U4.31(PIO0_0/INT0) ; port INT0
NetU4_32: U4.32(PIO0_1_GPIO_EN) ; port GPIO_PIO0_1
NetU4_37: U4.37(PIO0_3/PINT1) ; port PINT1
NetU4_38: U4.38(PIO0_4/PINT2) ; port PINT2
NetU4_39: U4.39(PIO0_5/FC6_MOSI) ; port FC6_MOSI
NetU4_40: U4.40(PIO0_6/FC6_MISO) ; port FC6_MISO
NetU4_41: U4.41(PIO0_7/FC6_SCK) ; port FC6_SCK
NetU4_42: U4.42(PIO1_11/FC6_SSEL1) ; port FC6_SSEL1
NetU4_43: U4.43(PIO0_8/BL) ; port LCD_BL
NetU4_44: U4.44(PIO0_9/SD_nCS) ; port LCD_SD_nCS
NetU4_45: U4.45(PIO0_10/nRESET) ; port LCD_nRESET
NetU4_46: U4.46(PIO0_11/D/nC) ; port LCD_D/nC
NetU4_47: U4.47(PIO0_12/FC3_RXD) ; port FC3_RXD
NetU4_48: U4.48(PIO0_13/FC3_TXD) ; port FC3_TXD
NetU4_49: U4.49(PIO0_14/FC3_nCTS) ; port FC3_nCTS
NetU4_50: U4.50(PIO0_15/FC3_nRTS) ; port FC3_nRTS

Not connected (* = marked no-connect by the designer): IC3 3(IO4) 4(IO5) 5(IO6) 6(IO7) 7(IO8) 8(IO9) 10(IO10) 13(IO18) 14(IO19) 15(IO3) 16(IO2) 17(IO1) 18(IO0); P2 6* 7* 8*; U4 1(PIO0_23)* 7(PIO1_16)* 10(PIO1_17)* 36(PIO0_2)* 62(PIO1_15)* 63(PIO0_22)*

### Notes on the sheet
- boot configuration : from valid code in flash. see chapter 3.2 of datasheet.
- CX1 = CX2 = 2CL -  (CPad + CParasitic)
  Where:
  CL - Crystal load capacitance
  CPad - Pad capacitance of the RTCXIN and RTCXOUT pins (3 pF).
  CParasitic – Parasitic or stray capacitance of external circuit. (Datasheet p.90)
- (near SW4) press and hold during a manuel reset to restart in ISP mode.
- (near U4) USB LPC not used

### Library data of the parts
C62-C75 C78 C79 = Cap: Capacitor
D1-D4 = LED
D5 = BAT54W-HG3-08: Schottky Diodes & Rectifiers 30V Zener SKY DIODE SOD-123; MF: Vishay Semiconductors
FB5-FB7 = BLM15HG102SN1D: as FB1 on sheet  user_interface
IC3 = ESP32-C3-WROOM-02-N4: Integrated Circuit; Manufacturer_Name: Espressif Systems
P2 = CMP-2000-05523-1: Male Header, Pitch 1.27 mm, 2 x 5 Position, Height 4.55 mm, -40 to 85 degC, RoHS, Tape and Reel; Brand: FCI; Mating Post Length: 3.05mm; Voltage Rating: 125V; Contact resistance Max: 30MOhm; Number of Positions: 10; Pitch: 1.27mm; Current Rating: 1A; Stack Height: 3mm; Mounting Angle: Vertical; Package Version: Rev. J, 03/2013
R12-R22 = Res2: Resistor
SW3 SW4 = CMP-2000-05602-2: as SW1 on sheet  user_interface
TP19-TP23 = TestPoint
Y1 = CMP-40224-000019-1: CRYSTAL 32.768KHZ 12.5PF SMD; ESR (Equivalent Series Resistance): 80kR; Frequency Tolerance: 10ppm

## Sheet  ext_power_amplifier.SchDoc: RFID UHF READER
size A4; Address1: Hepia; Address2: Gaetan Passeri; Address3: TB 2020-2021; Revision: 2.0; SheetNumber: 5; SheetTotal: 7
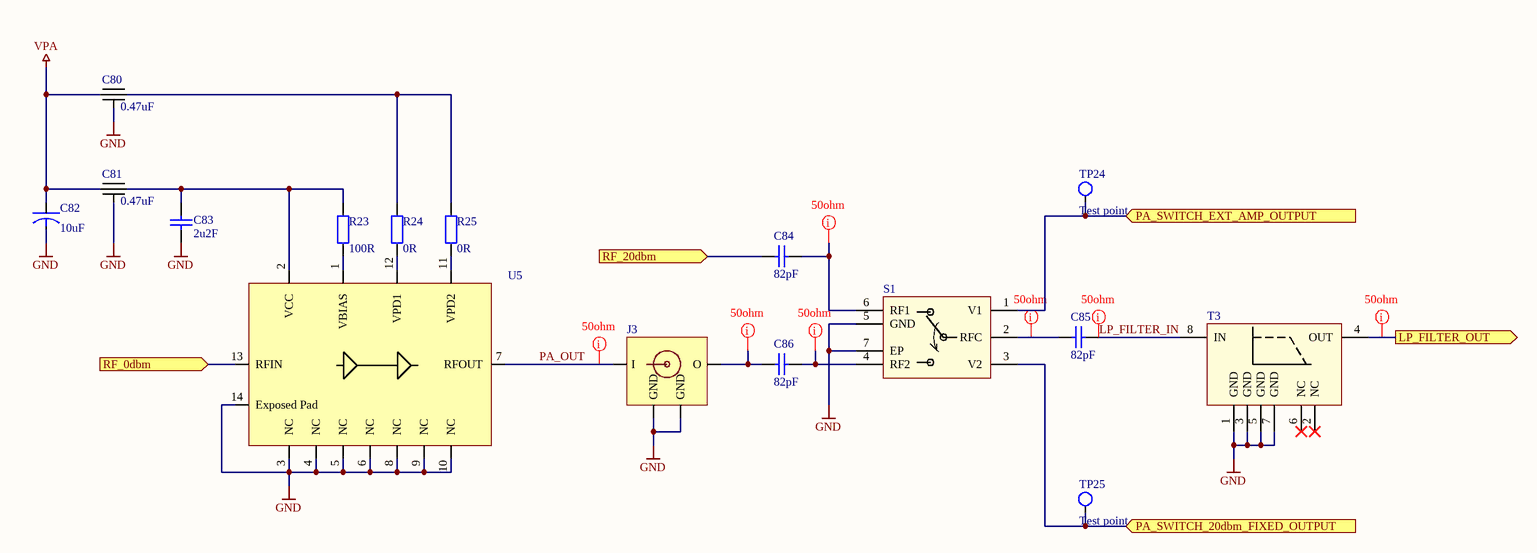
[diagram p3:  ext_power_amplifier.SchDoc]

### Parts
C80  0.47uF  [NFM18PS]
C81  0.47uF  [NFM18PS]
C82  10uF  [2917(7343)]
C83  value 2u2F  [FP-C0603C-CF-IPC_B]  (hidden comment: Cap)
C84  value 82pF  [FP-C0603C-CF-IPC_B]  (hidden comment: Cap)
C85  value 82pF  [FP-C0603C-CF-IPC_B]  (hidden comment: Cap)
C86  value 82pF  [FP-C0603C-CF-IPC_B]  (hidden comment: Cap)
J3  (no value)  [MS-156HF]
R23  value 100R  [FP-RC1608-IPC_B]  (hidden comment: Res2)
R24  value 0R  [FP-RC1608-IPC_B]  (hidden comment: Res2)
R25  value 0R  [FP-RC1608-IPC_B]  (hidden comment: Res2)
S1  (no value)  [SKY13431-374LF]
T3  (no value)  [JTI-0900LP15B0063]
TP24  Test point  [PIN_DE_TEST]
TP25  Test point  [PIN_DE_TEST]
U5  (no value)  [TQP9107]

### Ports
LP_FILTER_OUT (out), PA_SWITCH_20dbm_FIXED_OUTPUT (in), PA_SWITCH_EXT_AMP_OUTPUT (in), RF_0dbm (in), RF_20dbm (in)

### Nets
GND: C80.2 C81.2 C82.2 C83.1 J3.G1(GND) J3.G2(GND) S1.5(GND) S1.7(EP) T3.1(GND) T3.3(GND) T3.5(GND) T3.7(GND) U5.3(NC) U5.4(NC) U5.5(NC) U5.6(NC) U5.8(NC) U5.9(NC) U5.10(NC) U5.14(Exposed_Pad)
VPA: C80.1 C81.1 C82.1
LP_FILTER_IN: C85.2 T3.8(IN)
PA_OUT: J3.IN(I) U5.7(RFOUT)
NetC80_3: C80.3 R24.2 R25.2
NetC81_3: C81.3 C83.2 R23.2 U5.2(VCC)
NetC84_1: C84.1 ; port RF_20dbm
NetC84_2: C84.2 S1.6(RF1)
NetC85_1: C85.1 S1.2(RFC)
NetC86_1: C86.1 J3.OUT(O)
NetC86_2: C86.2 S1.4(RF2)
NetR23_1: R23.1 U5.1(VBIAS)
NetR24_1: R24.1 U5.12(VPD1)
NetR25_1: R25.1 U5.11(VPD2)
NetS1_1: S1.1(V1) TP24.1(tp) ; port PA_SWITCH_EXT_AMP_OUTPUT
NetS1_3: S1.3(V2) TP25.1(tp) ; port PA_SWITCH_20dbm_FIXED_OUTPUT
NetT3_4: T3.4(OUT) ; port LP_FILTER_OUT
NetU5_13: U5.13(RFIN) ; port RF_0dbm

Not connected (* = marked no-connect by the designer): T3 2(NC)* 6(NC)*

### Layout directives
rule Impedance Constraint [Min = 50.00    Max = 50.00    ]: LP_FILTER_IN, NetC84_2, NetC85_1, NetC86_1, NetC86_2, NetT3_4, PA_OUT

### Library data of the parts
C80 C81 = NFM18PS474R0J3D_1: as C11 on sheet  rf_interface
C82 = ECASD41C106M060K00: as C15 on sheet  rf_interface
C83-C86 = Cap: type : free, 0603, 20%
J3 = MS-156HF: as J1 on sheet  rf_interface
R23-R25 = Res2: Resistor
S1 = SKY13431-374LF: IC SWITCH SP2T; Manufacturer: Skyworks Solutions Inc.; Frequency - Lower: 500MHz; Isolation @ Frequency: 20dB @ 5.8GHz (typ); Insertion Loss @ Frequency: 0.8dB @ 5.8GHz; IIP3: 57dBm (typ); Circuit: SPDT; P1dB: 36dBm; Impedance: 50 Ohm; Voltage - Supply: 2.5 V ~ 5 V; RF Type: WiMax, WLAN
T3 = 0900LP15B0063: FILTER LOWPASS 863-960MHZ; Manufacturer: Johanson Technology Inc.; Manufacturer Part Number: 0900LP15B0063E
TP24 TP25 = TestPoint
U5 = TQP9107: 699 – 960 MHz 2-stage Power Amplifier; Manufacturer: Qorvo

## Sheet  coupling.SchDoc: RFID UHF READER
size A4; Address1: Hepia; Address2: Gaetan Passeri; Address3: TB 2020-2021; Revision: 2.0; SheetNumber: 6; SheetTotal: 7
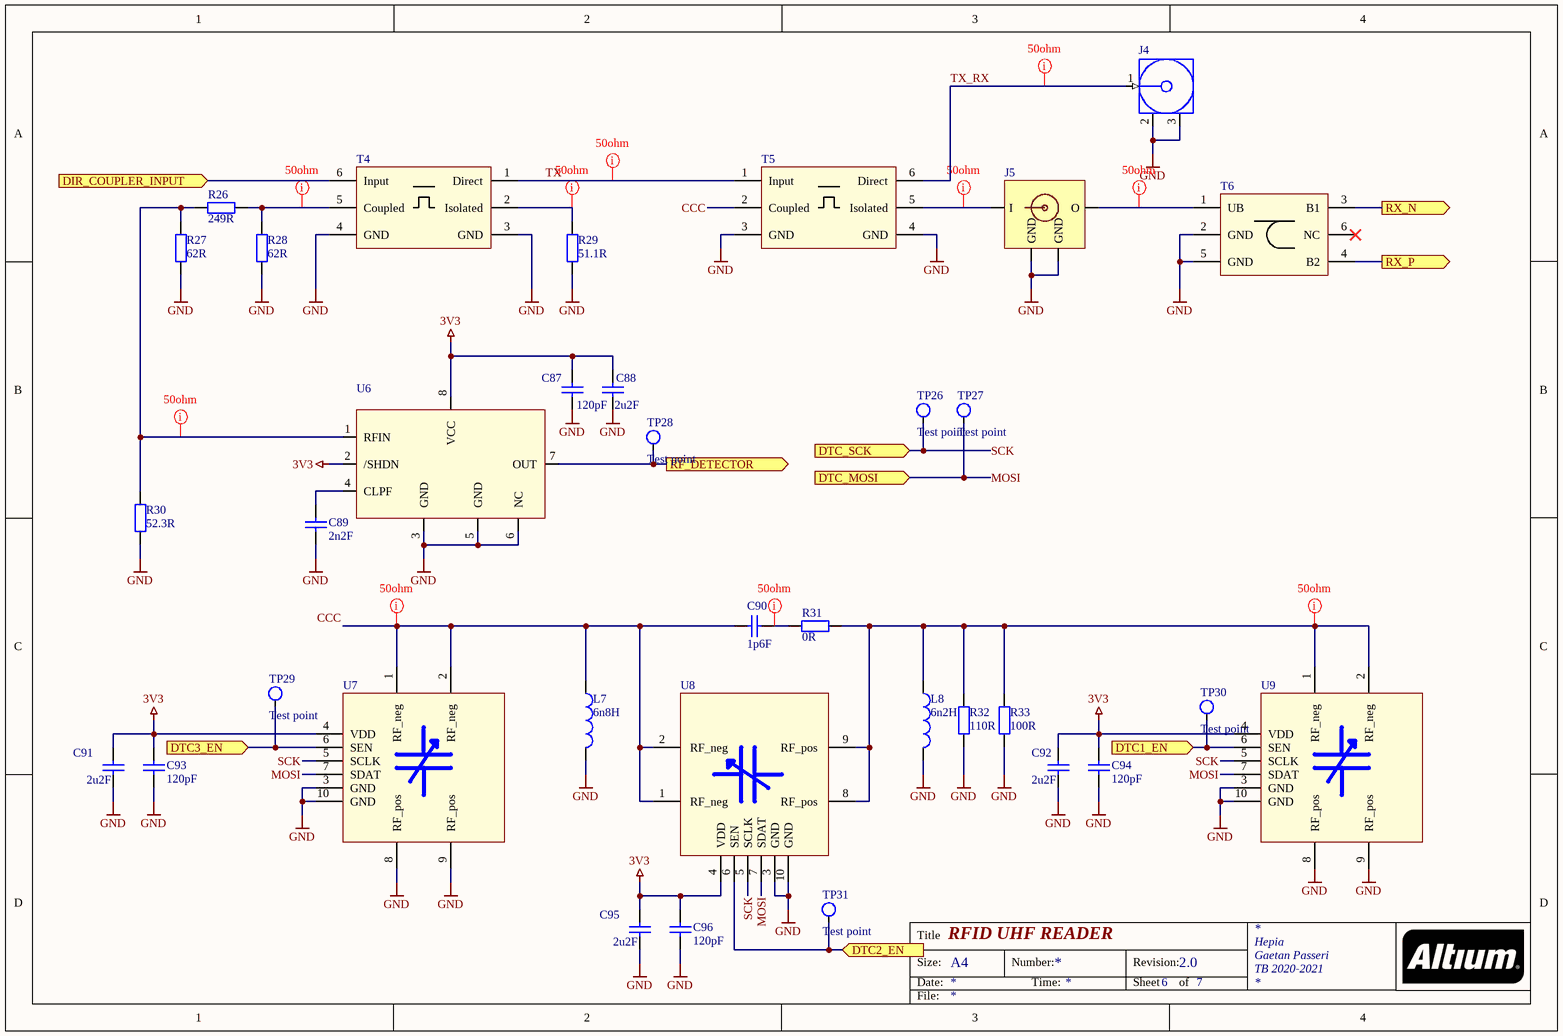
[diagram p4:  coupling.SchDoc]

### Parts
C87  value 120pF  [FP-PRF15-0_05-IPC_A]  (hidden comment: Cap)
C88  value 2u2F  [FP-PRF15-0_05-IPC_A]  (hidden comment: Cap)
C89  value 2n2F  [FP-PRF15-0_05-IPC_A]  (hidden comment: Cap)
C90  value 1p6F  [FP-PRF15-0_05-MFG]  (hidden comment: Cap)
C91  value 2u2F  [FP-PRF15-0_05-IPC_A]  (hidden comment: Cap)
C92  value 2u2F  [FP-PRF15-0_05-IPC_A]  (hidden comment: Cap)
C93  value 120pF  [FP-PRF15-0_05-IPC_A]  (hidden comment: Cap)
C94  value 120pF  [FP-PRF15-0_05-IPC_A]  (hidden comment: Cap)
C95  value 2u2F  [FP-PRF15-0_05-IPC_A]  (hidden comment: Cap)
C96  value 120pF  [FP-PRF15-0_05-IPC_A]  (hidden comment: Cap)
J4  (no value)  [FP-U_FL-R-SMT-1_10-MFG]
J5  (no value)  [MS-156HF]
L7  value 6n8H  [FP-LQG15HH_02-IPC_A]  (hidden comment: Inductor)
L8  value 6n2H  [FP-LQG15HH_02-IPC_A]  (hidden comment: Inductor)
R26  value 249R  [FP-RC1608-IPC_B]  (hidden comment: Res2)
R27  value 62R  [FP-RC1608-IPC_B]  (hidden comment: Res2)
R28  value 62R  [FP-RC1608-IPC_B]  (hidden comment: Res2)
R29  value 51.1R  [FP-RC1608-IPC_B]  (hidden comment: Res2)
R30  value 52.3R  [FP-RC1608-IPC_B]  (hidden comment: Res2)
R31  value 0R  [FP-RC1005-IPC_A]  (hidden comment: Res2)
R32  value 110R  [FP-RC1005-IPC_A]  (hidden comment: Res2)
R33  value 100R  [FP-RC1005-IPC_A]  (hidden comment: Res2)
T4  (no value)  [DC0710J5010AHF]
T5  (no value)  [DC0710J5010AHF]
T6  (no value)  [BD0810J50100AHF]
TP26  Test point  [PIN_DE_TEST]
TP27  Test point  [PIN_DE_TEST]
TP28  Test point  [PIN_DE_TEST]
TP29  Test point  [PIN_DE_TEST]
TP30  Test point  [PIN_DE_TEST]
TP31  Test point  [PIN_DE_TEST]
U6  (no value)  [MAX4003]
U7  (no value)  [PE62304]
U8  (no value)  [PE62304]
U9  (no value)  [PE62304]

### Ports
DIR_COUPLER_INPUT (in), DTC1_EN (in), DTC2_EN (in), DTC3_EN (in), DTC_MOSI (in), DTC_SCK (in), RF_DETECTOR (out), RX_N (out), RX_P (out)

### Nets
3V3: C87.2 C88.2 C91.1 C92.1 C93.1 C94.1 C95.1 C96.1 U6.2(/SHDN) U6.8(VCC) U7.4(VDD) U8.4(VDD) U9.4(VDD)
GND: C87.1 C88.1 C89.1 C91.2 C92.2 C93.2 C94.2 C95.2 C96.2 J4.2(GND) J4.3(GND) J5.G1(GND) J5.G2(GND) L7.2 L8.2 R27.2 R28.2 R29.2 R30.2 R32.2 R33.2 T4.3(GND) T4.4(GND) T5.3(GND) T5.4(GND) T6.2(GND) T6.5(GND) U6.3(GND) U6.5(GND) U6.6(NC) U7.3(GND) U7.8(RF_pos) U7.9(RF_pos) U7.10(GND) U8.3(GND) U8.10(GND) U9.3(GND) U9.8(RF_pos) U9.9(RF_pos) U9.10(GND)
CCC: C90.2 L7.1 T5.2(Coupled) U7.1(RF_neg) U7.2(RF_neg) U8.1(RF_neg) U8.2(RF_neg)
MOSI: TP27.1(tp) U7.7(SDAT) U8.7(SDAT) U9.7(SDAT) ; port DTC_MOSI
SCK: TP26.1(tp) U7.5(SCLK) U8.5(SCLK) U9.5(SCLK) ; port DTC_SCK
TX: T4.1(Direct) T5.1(Input)
TX_RX: J4.1(Signal) T5.6(Direct)
NetC89_2: C89.2 U6.4(CLPF)
NetC90_1: C90.1 R31.1
NetJ5_IN: J5.IN(I) T5.5(Isolated)
NetJ5_OUT: J5.OUT(O) T6.1(UB)
NetL8_1: L8.1 R31.2 R32.1 R33.1 U8.8(RF_pos) U8.9(RF_pos) U9.1(RF_neg) U9.2(RF_neg)
NetR26_1: R26.1 R28.1 T4.5(Coupled)
NetR26_2: R26.2 R27.1 R30.1 U6.1(RFIN)
NetR29_1: R29.1 T4.2(Isolated)
NetT4_6: T4.6(Input) ; port DIR_COUPLER_INPUT
NetT6_3: T6.3(B1) ; port RX_N
NetT6_4: T6.4(B2) ; port RX_P
NetTP28_1: TP28.1(tp) U6.7(OUT) ; port RF_DETECTOR
NetTP29_1: TP29.1(tp) U7.6(SEN) ; port DTC3_EN
NetTP30_1: TP30.1(tp) U9.6(SEN) ; port DTC1_EN
NetTP31_1: TP31.1(tp) U8.6(SEN) ; port DTC2_EN

Not connected (* = marked no-connect by the designer): T6 6(NC)*

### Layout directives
rule Impedance Constraint [Min = 50.00    Max = 50.00    ]: CCC, NetC90_1, NetJ5_IN, NetJ5_OUT, NetL8_1, NetR26_1, NetR26_2, NetR29_1, TX, TX_RX

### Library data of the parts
C87-C96 = Cap: type : free, 0603, 20%
J4 = CMP-0168-00038-1: SMA Female Edge Multi-Mount Connector for 0.031" Thick Board; PCB_Layout: Pads complies with manufacturer's recommendation.
J5 = MS-156HF: as J1 on sheet  rf_interface
L7 L8 = Inductor: Code_IEC: 1005
R26-R33 = Res2: Resistor
T4 = DC0710J5020AHF: COUPLER 20DB 700-1000MHZ 0805; Manufacturer: Anaren; Frequency: 700MHz; Insertion Loss: 0.22dB; Max Power Dissipation: 2W; Return Loss: 21.41dB
T5 = DC0710J5010AHF: Directional Coupler; Manufacturer: Anaren; Coupler Type: Standard; Frequency: 700MHz ~ 1GHz; Coupling Factor: 10.9dB; Insertion Loss: 0.21dB; Power - Max: 2W; Return Loss: 17.5dB
T6 = BD0810J50100AHF: as T1 on sheet  rf_interface
TP26-TP31 = TestPoint
U6 = MAX4003EUA+T: IC LOG AMP RF DETECT 45DB 8-MSOP; Manufacturer: Maxim Integrated; Frequency: 100MHz ~ 2.5GHz; RF Type: Cellular, TDMA, CDMA, GPRS, GSM; Input Range: -45dBm ~ 0dBm; Voltage - Supply: 2.7 V ~ 5 V
U7-U9 = PE64906MLAA-Z: IC RF DTC 100-3000MHZ 10QFN; Manufacturer: Peregrine Semiconductor; Function: Digitally Tunable Capacitor; Frequency: 100MHz ~ 3GHz; RF Type: General Purpose; Secondary Attributes: SPI Interface; Exact Component Match: yes; Frequency - Lower: 500MHz; Isolation @ Frequency: 20dB @ 5.8GHz (typ); Insertion Loss @ Frequency: 0.8dB @ 5.8GHz; IIP3: 57dBm (typ); Circuit: SPDT; P1dB: 36dBm; Impedance: 50 Ohm; Voltage - Supply: 2.5 V ~ 5 V

## Sheet  baseStation.SchDoc: RFID UHF READER
size A4; Date: 19.03.2021; Author: Gaetan Passeri; CompanyName: HEPIA; DrawnBy: Gaetan Passeri; Address1: Hepia; Address2: Gaetan Passeri; Address3: TB 2020-2021; Revision: 2.0; SheetNumber: 1; SheetTotal: 7
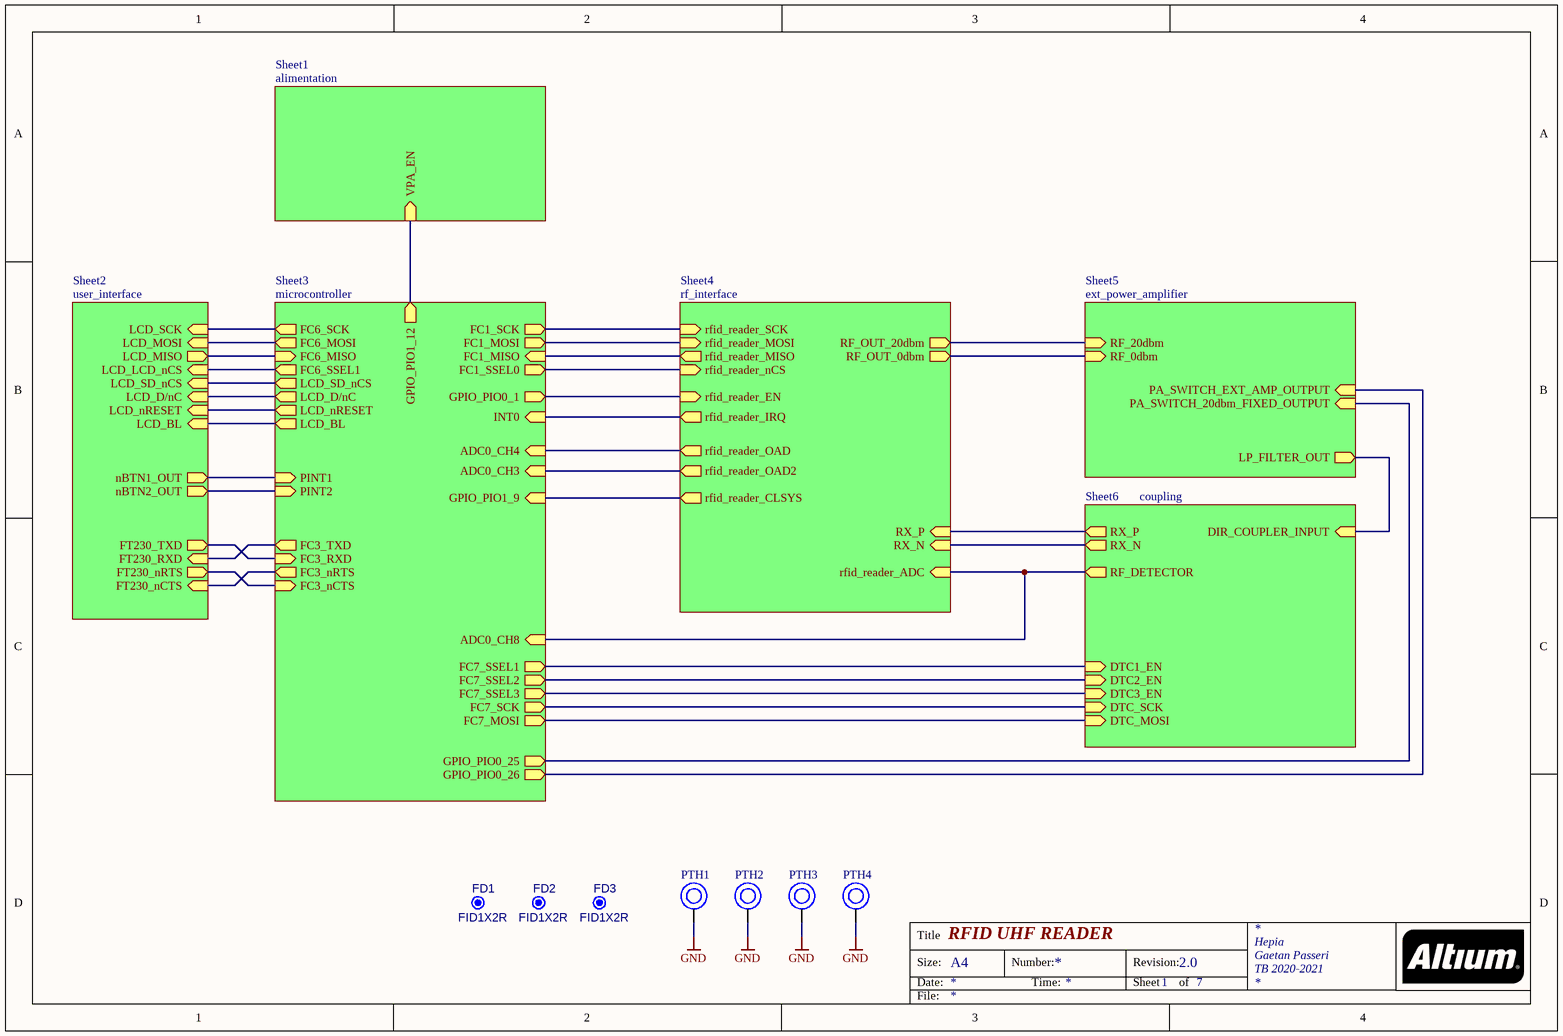
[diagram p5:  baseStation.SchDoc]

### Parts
FD1  FID1X2R  [FID1X2R]  (no BOM)
FD2  FID1X2R  [FID1X2R]  (no BOM)
FD3  FID1X2R  [FID1X2R]  (no BOM)
PTH1  mounting hole  [M3-hole]  (value not drawn)
PTH2  mounting hole  [M3-hole]  (value not drawn)
PTH3  mounting hole  [M3-hole]  (value not drawn)
PTH4  mounting hole  [M3-hole]  (value not drawn)

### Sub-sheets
Sheet1 = alimentation (file not in this document): VPA_EN (in)
Sheet2 = user_interface (file not in this document): FT230_RXD (in), FT230_TXD (out), FT230_nCTS (in), FT230_nRTS (out), LCD_nRESET (in), LCD_D/nC (in), LCD_MISO (out), LCD_BL (in), LCD_MOSI (in), LCD_SCK (in), LCD_SD_nCS (in), nBTN2_OUT (out), nBTN1_OUT (out), LCD_LCD_nCS (in)
Sheet3 = microcontroller (file not in this document): FC6_MOSI (out), FC6_SSEL1 (out), FC6_MISO (in), FC6_SCK (out), FC3_RXD (in), FC3_TXD (out), PINT1 (in), FC3_nRTS (out), FC3_nCTS (in), PINT2 (in), LCD_nRESET (out), LCD_D/nC (out), LCD_SD_nCS (out), LCD_BL (out), FC1_MISO (in), FC1_MOSI (out), FC1_SSEL0 (out), FC1_SCK (out), GPIO_PIO0_1 (out), INT0 (in), ADC0_CH3 (in), ADC0_CH4 (in), GPIO_PIO1_9 (in), ADC0_CH8 (in), FC7_SSEL3 (out), FC7_SSEL2 (out), FC7_SSEL1 (out), FC7_MOSI (out), FC7_SCK (out), GPIO_PIO0_26 (out), GPIO_PIO0_25 (out), GPIO_PIO1_12 (out)
Sheet4 = rf_interface (file not in this document): rfid_reader_OAD2 (out), rfid_reader_ADC (in), rfid_reader_EN (in), RX_N (in), rfid_reader_OAD (out), RX_P (in), RF_OUT_20dbm (out), RF_OUT_0dbm (out), rfid_reader_MISO (out), rfid_reader_MOSI (in), rfid_reader_SCK (in), rfid_reader_IRQ (out), rfid_reader_CLSYS (out), rfid_reader_nCS (in)
Sheet5 = ext_power_amplifier (file not in this document): PA_SWITCH_EXT_AMP_OUTPUT (in), LP_FILTER_OUT (out), PA_SWITCH_20dbm_FIXED_OUTPUT (in), RF_20dbm (in), RF_0dbm (in)
Sheet6 = coupling (file not in this document): DTC1_EN (in), DTC2_EN (in), RX_N (out), DTC_SCK (in), RX_P (out), RF_DETECTOR (out), DTC_MOSI (in), DTC3_EN (in), DIR_COUPLER_INPUT (in)

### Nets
GND: PTH1.1 PTH2.1 PTH3.1 PTH4.1
(unnamed): sheet Sheet3/FC6_MOSI, sheet Sheet2/LCD_MOSI
(unnamed): sheet Sheet3/FC6_SSEL1, sheet Sheet2/LCD_LCD_nCS  [a separate net that carries the same name]
(unnamed): sheet Sheet3/FC6_MISO, sheet Sheet2/LCD_MISO  [a separate net that carries the same name]
(unnamed): sheet Sheet3/FC6_SCK, sheet Sheet2/LCD_SCK  [a separate net that carries the same name]
(unnamed): sheet Sheet3/FC3_RXD, sheet Sheet2/FT230_TXD  [a separate net that carries the same name]
(unnamed): sheet Sheet3/FC3_TXD, sheet Sheet2/FT230_RXD  [a separate net that carries the same name]
(unnamed): sheet Sheet3/PINT1, sheet Sheet2/nBTN1_OUT  [a separate net that carries the same name]
(unnamed): sheet Sheet3/FC3_nRTS, sheet Sheet2/FT230_nCTS  [a separate net that carries the same name]
(unnamed): sheet Sheet3/FC3_nCTS, sheet Sheet2/FT230_nRTS  [a separate net that carries the same name]
(unnamed): sheet Sheet3/PINT2, sheet Sheet2/nBTN2_OUT  [a separate net that carries the same name]
(unnamed): sheet Sheet3/LCD_nRESET, sheet Sheet2/LCD_nRESET  [a separate net that carries the same name]
(unnamed): sheet Sheet3/LCD_D/nC, sheet Sheet2/LCD_D/nC  [a separate net that carries the same name]
(unnamed): sheet Sheet3/LCD_SD_nCS, sheet Sheet2/LCD_SD_nCS  [a separate net that carries the same name]
(unnamed): sheet Sheet3/LCD_BL, sheet Sheet2/LCD_BL  [a separate net that carries the same name]
(unnamed): sheet Sheet3/FC1_MISO, sheet Sheet4/rfid_reader_MISO  [a separate net that carries the same name]
(unnamed): sheet Sheet3/FC1_MOSI, sheet Sheet4/rfid_reader_MOSI  [a separate net that carries the same name]
(unnamed): sheet Sheet3/FC1_SSEL0, sheet Sheet4/rfid_reader_nCS  [a separate net that carries the same name]
(unnamed): sheet Sheet3/FC1_SCK, sheet Sheet4/rfid_reader_SCK  [a separate net that carries the same name]
(unnamed): sheet Sheet3/GPIO_PIO0_1, sheet Sheet4/rfid_reader_EN  [a separate net that carries the same name]
(unnamed): sheet Sheet3/INT0, sheet Sheet4/rfid_reader_IRQ  [a separate net that carries the same name]
(unnamed): sheet Sheet3/ADC0_CH3, sheet Sheet4/rfid_reader_OAD2  [a separate net that carries the same name]
(unnamed): sheet Sheet3/ADC0_CH4, sheet Sheet4/rfid_reader_OAD  [a separate net that carries the same name]
(unnamed): sheet Sheet3/GPIO_PIO1_9, sheet Sheet4/rfid_reader_CLSYS  [a separate net that carries the same name]
(unnamed): sheet Sheet3/ADC0_CH8, sheet Sheet4/rfid_reader_ADC, sheet Sheet6/RF_DETECTOR  [a separate net that carries the same name]
(unnamed): sheet Sheet3/FC7_SSEL3, sheet Sheet6/DTC3_EN  [a separate net that carries the same name]
(unnamed): sheet Sheet3/FC7_SSEL2, sheet Sheet6/DTC2_EN  [a separate net that carries the same name]
(unnamed): sheet Sheet3/FC7_SSEL1, sheet Sheet6/DTC1_EN  [a separate net that carries the same name]
(unnamed): sheet Sheet3/FC7_MOSI, sheet Sheet6/DTC_MOSI  [a separate net that carries the same name]
(unnamed): sheet Sheet3/FC7_SCK, sheet Sheet6/DTC_SCK  [a separate net that carries the same name]
(unnamed): sheet Sheet3/GPIO_PIO0_26, sheet Sheet5/PA_SWITCH_EXT_AMP_OUTPUT  [a separate net that carries the same name]
(unnamed): sheet Sheet3/GPIO_PIO0_25, sheet Sheet5/PA_SWITCH_20dbm_FIXED_OUTPUT  [a separate net that carries the same name]
(unnamed): sheet Sheet3/GPIO_PIO1_12, sheet Sheet1/VPA_EN  [a separate net that carries the same name]
(unnamed): sheet Sheet4/RX_N, sheet Sheet6/RX_N  [a separate net that carries the same name]
(unnamed): sheet Sheet4/RX_P, sheet Sheet6/RX_P  [a separate net that carries the same name]
(unnamed): sheet Sheet4/RF_OUT_20dbm, sheet Sheet5/RF_20dbm  [a separate net that carries the same name]
(unnamed): sheet Sheet4/RF_OUT_0dbm, sheet Sheet5/RF_0dbm  [a separate net that carries the same name]
(unnamed): sheet Sheet5/LP_FILTER_OUT, sheet Sheet6/DIR_COUPLER_INPUT  [a separate net that carries the same name]

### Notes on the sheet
- fallback solution. The RF detector output isn't connected to the ST25RU3993 by default. the 0ohm resistor must be unmounted. The ST25RU3993 measure the power internally via its RX_P/N mix  inputs!

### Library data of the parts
FD1-FD3 = CMP-00028-00005-1: Fiducial - Round 1x2mm
PTH1-PTH4 = mounting hole: M3 mounting hole

## Sheet  alimentation.SchDoc: RFID UHF READER
size A4; Date: 19.03.2021; Author: Gaetan Passeri; CompanyName: HEPIA; DrawnBy: Gaetan Passeri; Address1: Hepia; Address2: Gaetan Passeri; Address3: TB 2020-2021; Revision: 2.0; SheetNumber: 7; SheetTotal: 7
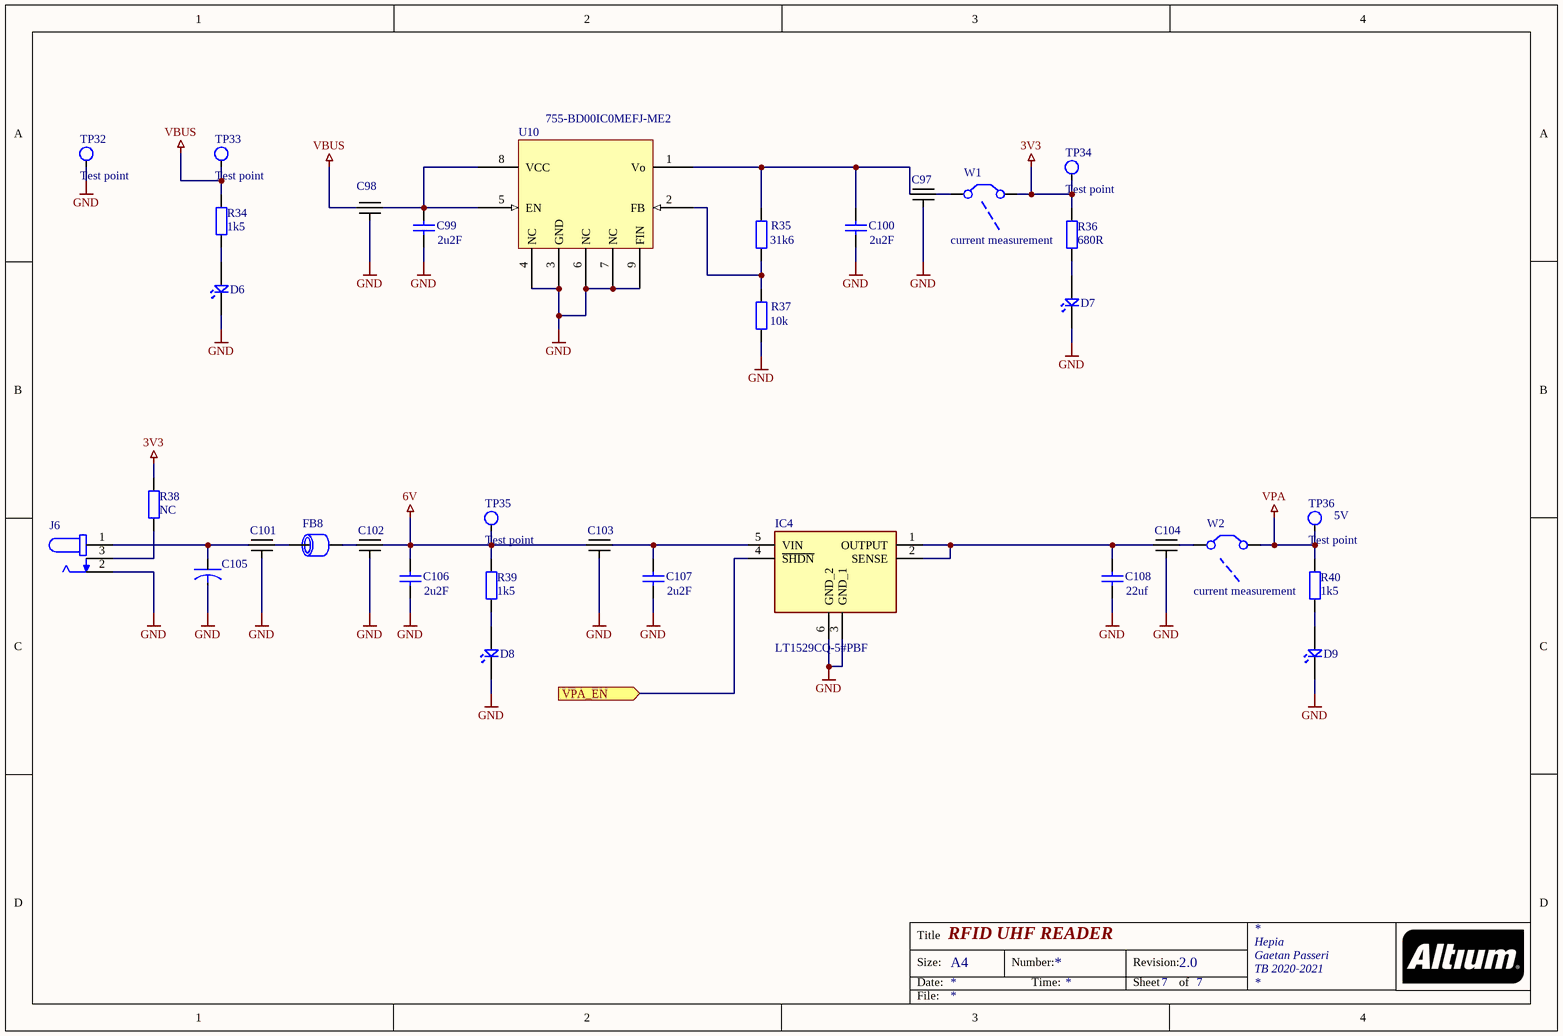
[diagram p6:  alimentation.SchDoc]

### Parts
C97  (no value)  [NFM18PS]
C98  (no value)  [NFM18PS]
C99  value 2u2F  [FP-C0805C-DN-IPC_B]  (hidden comment: Cap)
C100  value 2u2F  [FP-C0805C-DN-IPC_B]  (hidden comment: Cap)
C101  (no value)  [NFM18PS]
C102  (no value)  [NFM18PS]
C103  (no value)  [NFM18PS]
C104  (no value)  [NFM18PS]
C105  (no value)  [2917(7343)]
C106  value 2u2F  [FP-C0805C-DN-IPC_B]  (hidden comment: Cap)
C107  value 2u2F  [FP-C0805C-DN-IPC_B]  (hidden comment: Cap)
C108  value 22uf  [FP-C0805C-DN-IPC_B]  (hidden comment: Cap)
D6  (no value)  [LTST-C170KRKT_V]
D7  (no value)  [LTST-C170KRKT_V]
D8  (no value)  [LTST-C170KRKT_V]
D9  (no value)  [LTST-C170KRKT_V]
FB8  (no value)  [FB0402-RF]
IC4  LT1529CQ-5#PBF  [LT1529CQ5PBF]
J6  (no value)  [CUI_PJ-036BH-SMT-TR]
R34  value 1k5  [FP-RC1608-IPC_B]
R35  value 31k6  [FP-RC1608-IPC_B]
R36  value 680R  [FP-RC1608-IPC_B]
R37  value 10k  [FP-RC1608-IPC_B]
R38  value NC  [FP-RC1608-IPC_B]
R39  value 1k5  [FP-RC1608-IPC_B]
R40  value 1k5  [FP-RC1608-IPC_B]
TP32  Test point  [PIN_DE_TEST]
TP33  Test point  [PIN_DE_TEST]
TP34  Test point  [PIN_DE_TEST]
TP35  Test point  [PIN_DE_TEST]
TP36  Test point  [PIN_DE_TEST]
U10  755-BD00IC0MEFJ-ME2  [HTSOP-J8]
W1  current measurement  [PLUG_THMD_STRIP2]
W2  current measurement  [PLUG_THMD_STRIP2]

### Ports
VPA_EN (in)

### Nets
3V3: R36.2 R38.2 TP34.1(tp) W1.2(C2)
6V: C102.3 C103.1 C106.2 R39.2 TP35.1(tp)
GND: C97.2 C98.2 C99.1 C100.1 C101.2 C102.2 C103.2 C104.2 C105.2 C106.1 C107.1 C108.1 D6.K D7.K D8.K D9.K IC4.3(GND_1) IC4.6(GND_2) J6.2 R37.1 TP32.1(tp) U10.3(GND) U10.4(NC) U10.6(NC) U10.7(NC) U10.9(FIN)
VBUS: C98.1 R34.2 TP33.1(tp)
VPA: R40.2 TP36.1(tp) W2.2(C2)
NetC97_1: C97.1 C100.2 R35.2 U10.1(Vo)
NetC97_3: C97.3 W1.1(C1)
NetC98_3: C98.3 C99.2 U10.5(EN) U10.8(VCC)
NetC101_1: C101.1 C105.1 J6.1
NetC101_3: C101.3 FB8.1
NetC102_1: C102.1 FB8.2
NetC103_3: C103.3 C107.2 IC4.5(VIN)
NetC104_1: C104.1 C108.2 IC4.1(OUTPUT) IC4.2(SENSE)
NetC104_3: C104.3 W2.1(C1)
NetD6_A: D6.A R34.1
NetD7_A: D7.A R36.1
NetD8_A: D8.A R39.1
NetD9_A: D9.A R40.1
NetIC4_4: IC4.4(~{SHDN}) ; port VPA_EN
NetJ6_3: J6.3 R38.1
NetR35_1: R35.1 R37.2 U10.2(FB)

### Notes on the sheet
- (near TP36) 5V
- UF = 1,9V
  IF = 2mA
  R = (5 - 1,9) 2*10^-3 = 1550
  E12 => 1500 ohm
  => IF = (5-1,9)/1500 = 2,06 mA

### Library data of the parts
C97 C101-C104 = NFM18PS474R0J3D_1: as C11 on sheet  rf_interface
C98 = NFM18PS474R0J3D: CAP FEEDTHRU 0.47UF 6.3V 0603; Manufacturer: Murata Electronics North America; Capacitance: 0.47µF; Tolerance: ±20%; Current: 2A; DC Resistance (DCR) (Max): 30 mOhm; Type: Polymer; ESR (Equivalent Series Resistance): 70 mOhm; Lifetime @ Temp.: 1000 Hrs @ 105°C; Ripple Current - High Frequency: 1A @ 100kHz; Surface Mount Land Size: 0.287" L x 0.169" W (7.30mm x 4.30mm)
C99 C100 C106-C108 = Cap: ceramic
C105 = ECASD41C106M060K00: as C15 on sheet  rf_interface
D6-D9 = LED
FB8 = BLM15PX331SN1D: as FB3 on sheet  rf_interface
IC4 = LT1529CQ-5#PBF: Integrated Circuit; Manufacturer_Name: Analog Devices
J6 = PJ-036BH-SMT-TR: 2.5 x 6.3 mm, 5.0 A, Horizontal, Surface Mount _SMT_, Dc Power Jack Connector; MF: CUI Devices
R34-R40 = Res2: Resistor
TP32-TP36 = TestPoint
U10 = BD00IC0MEFJ-ME2: Régulateurs de tension LDO IC Pwr Linear Reg Single Output LDO
W1 W2 = Jumper: Jumper Wire

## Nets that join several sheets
3V3:  user_interface (R5.2 R6.2 U1.2),  rf_interface (7 pins),  microcontroller (12 pins),  coupling (13 pins),  alimentation (R36.2 R38.2 TP34.1 W1.2)
GND:  user_interface (21 pins),  rf_interface (59 pins),  microcontroller (36 pins),  ext_power_amplifier (20 pins),  coupling (40 pins),  baseStation (PTH1.1 PTH2.1 PTH3.1 PTH4.1),  alimentation (26 pins)
VBUS:  user_interface (R1.2),  alimentation (C98.1 R34.2 TP33.1)
VPA:  ext_power_amplifier (C80.1 C81.1 C82.1),  alimentation (R40.2 TP36.1 W2.2)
